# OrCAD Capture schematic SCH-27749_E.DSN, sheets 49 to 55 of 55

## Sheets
49 T4240 USB Ports: size C
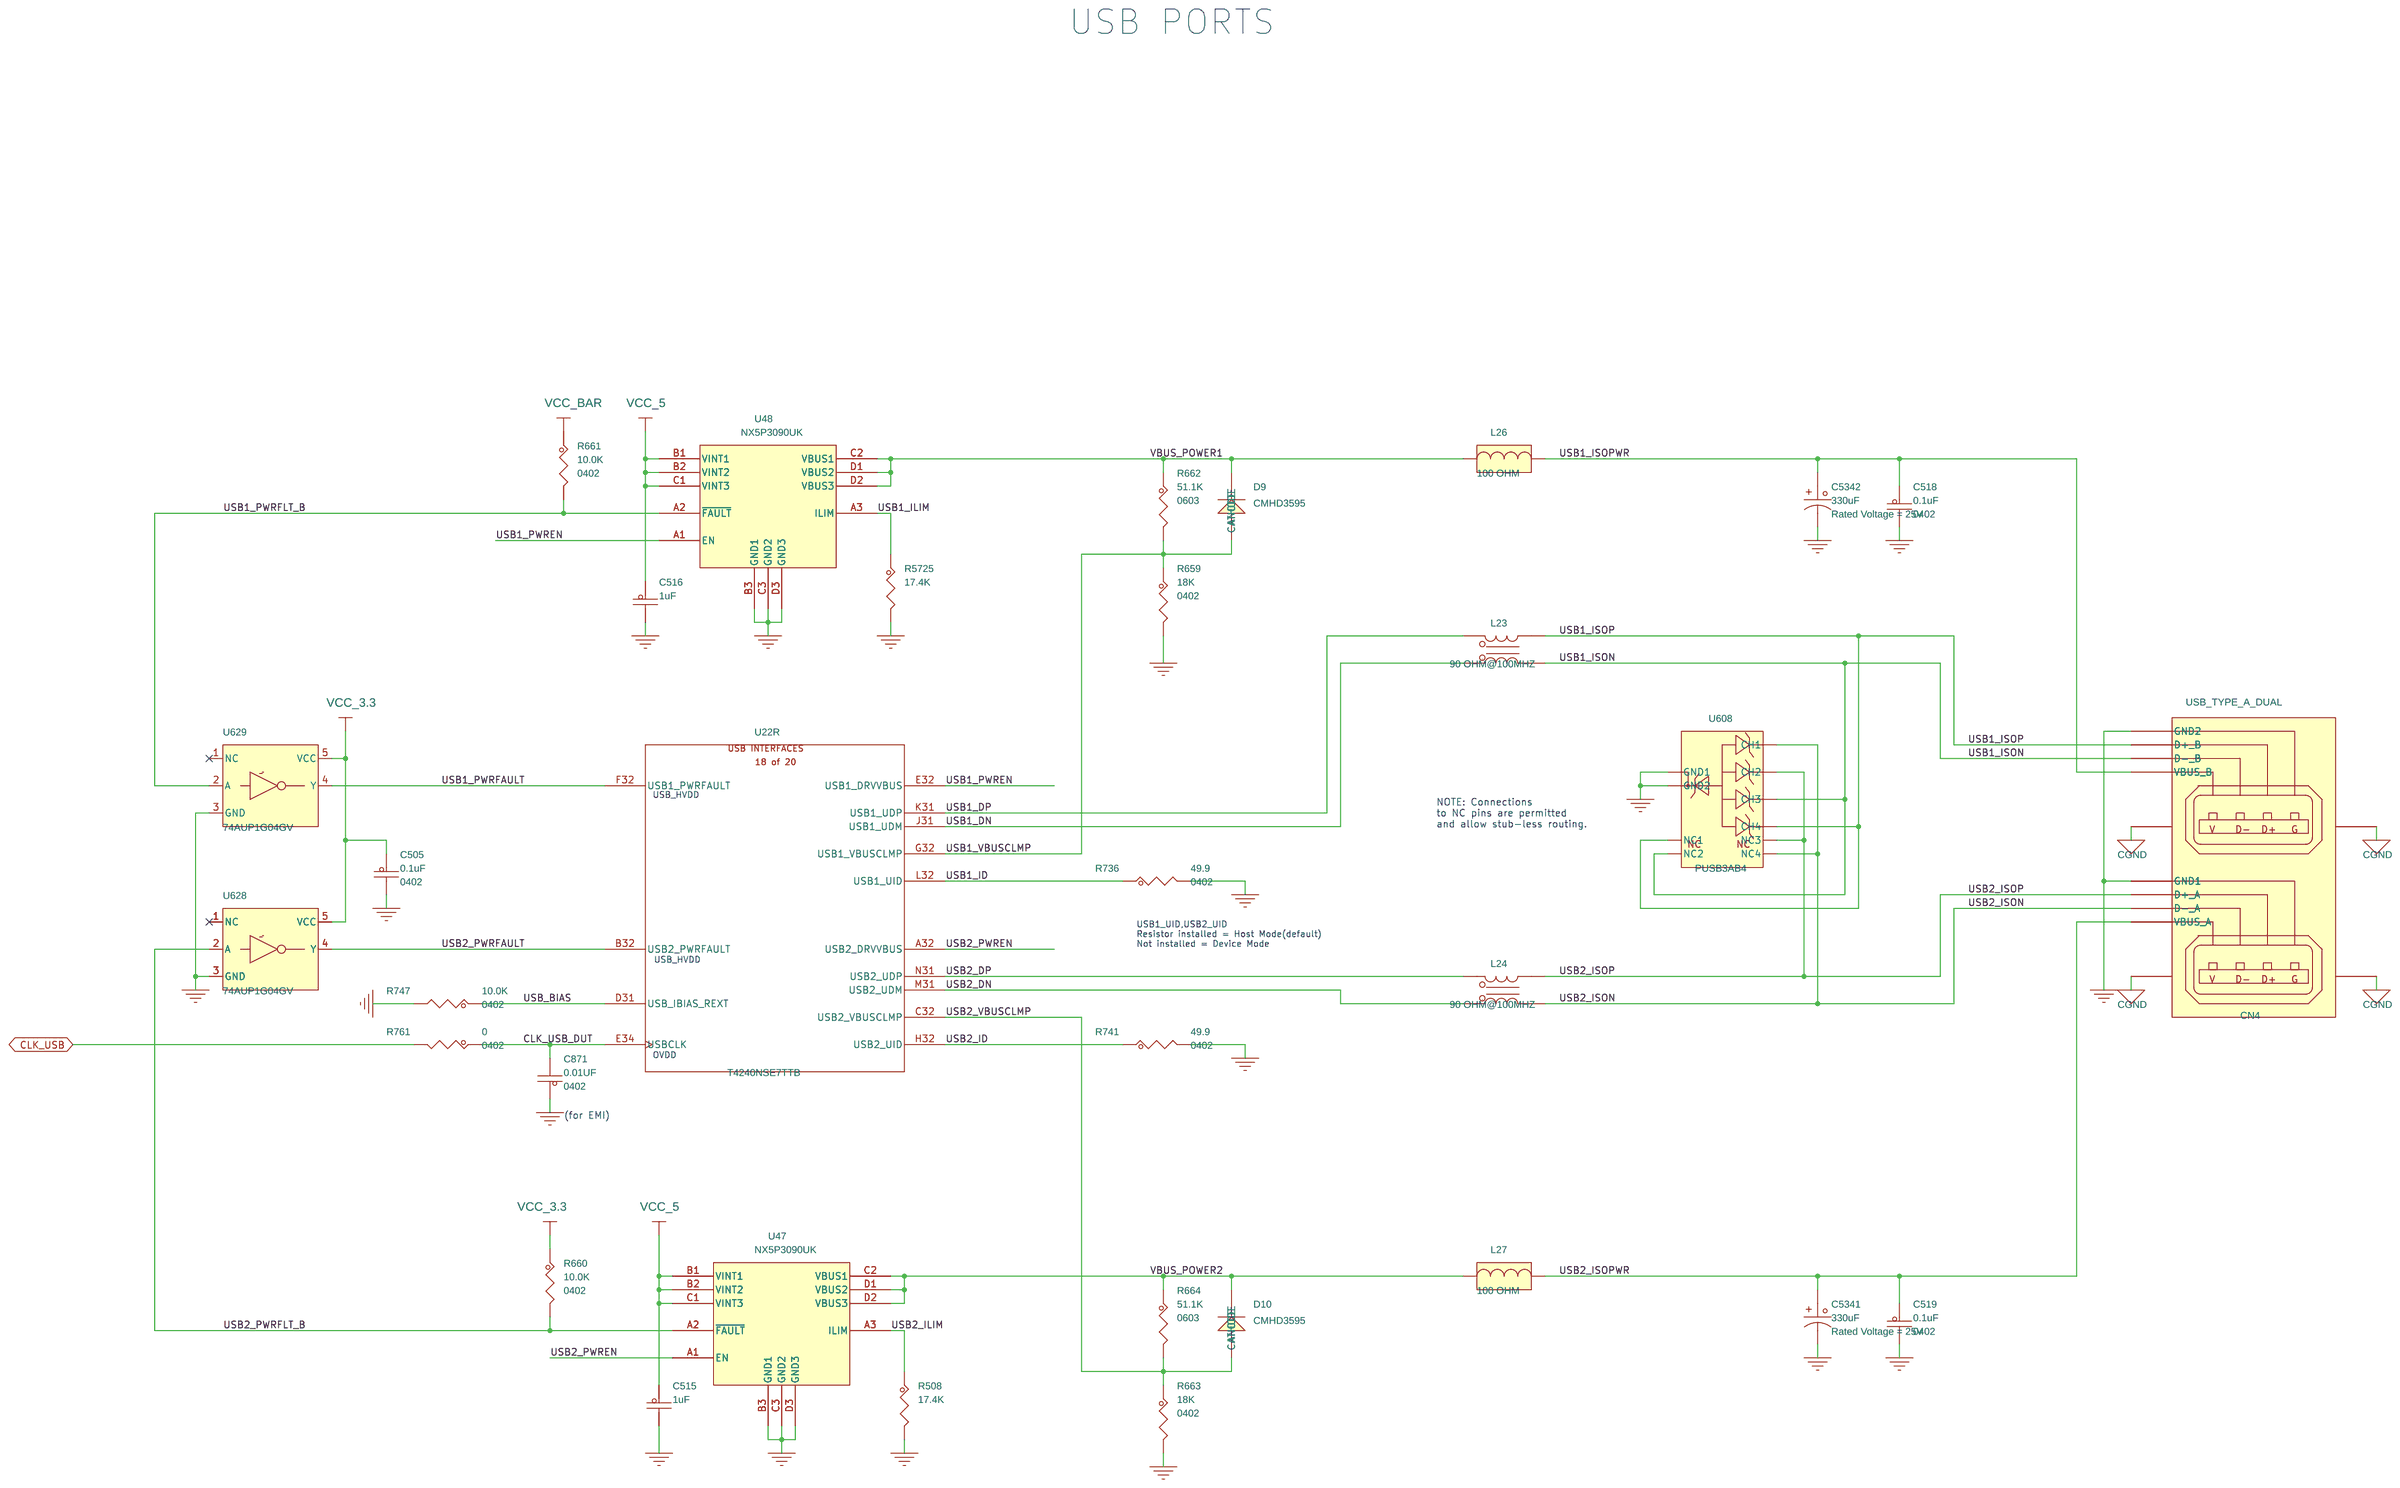
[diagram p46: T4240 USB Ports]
50 I2C Buf/Mux: size C
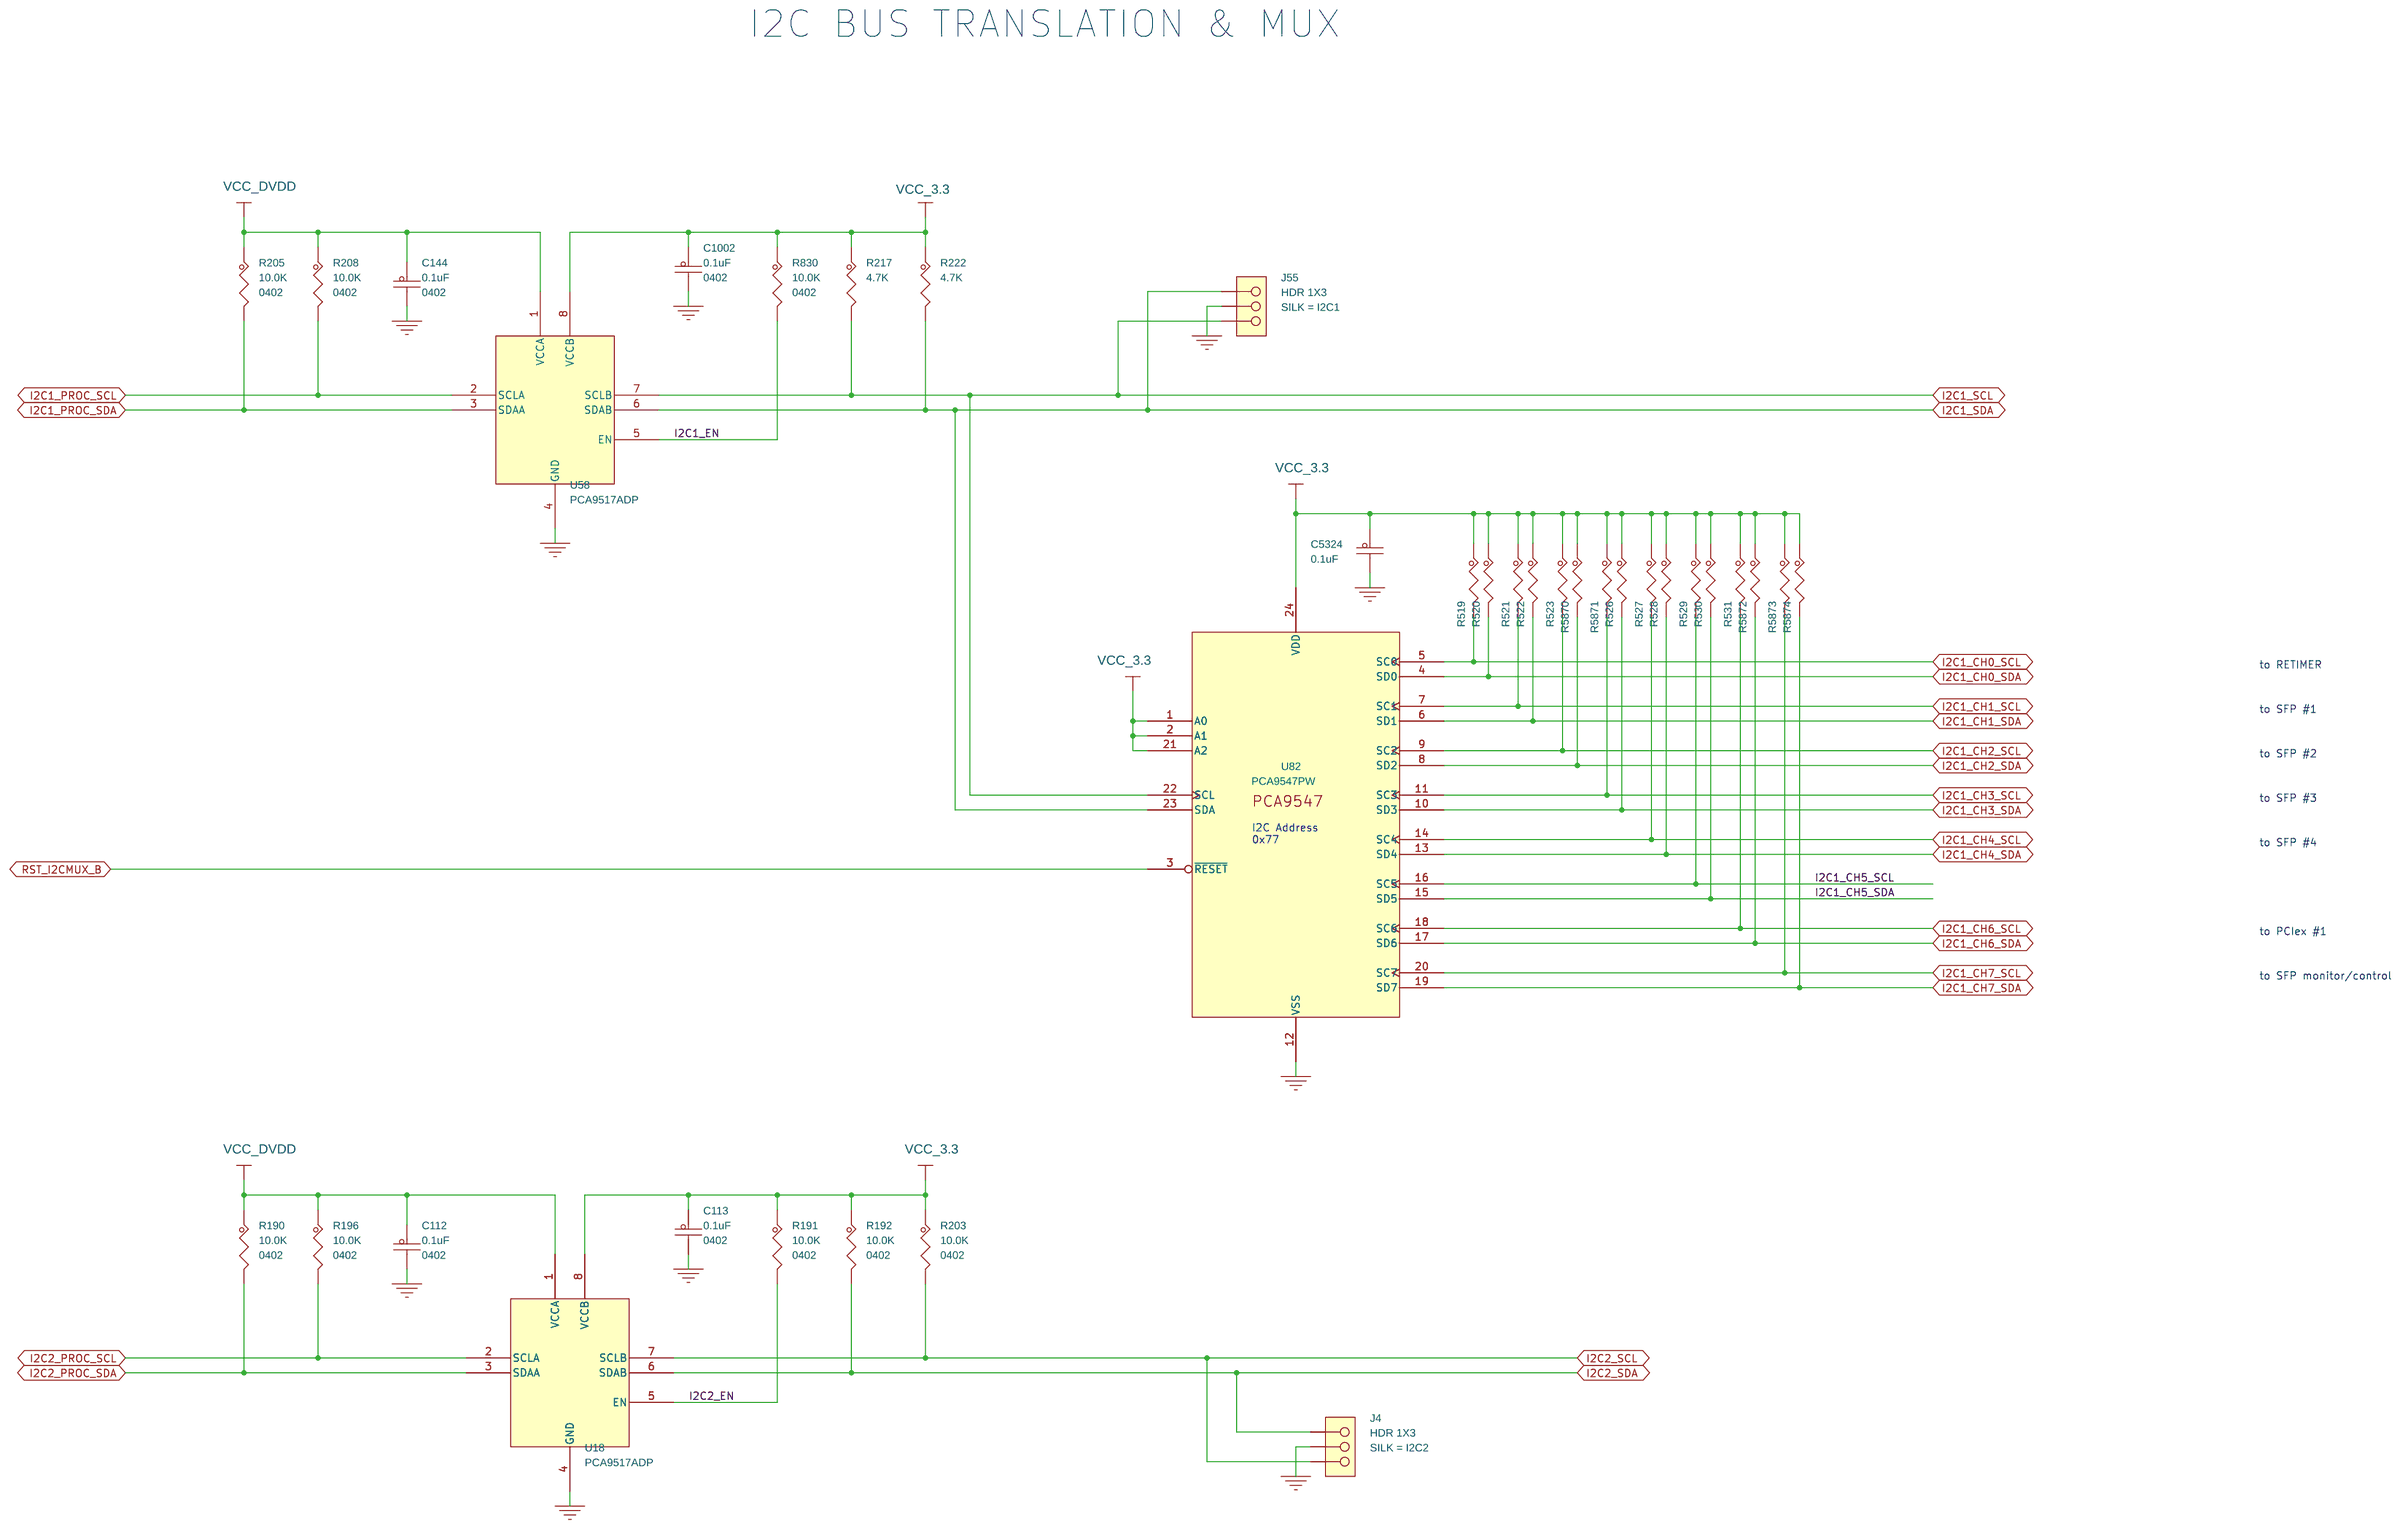
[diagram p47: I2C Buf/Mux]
51 I2C Devices: size C
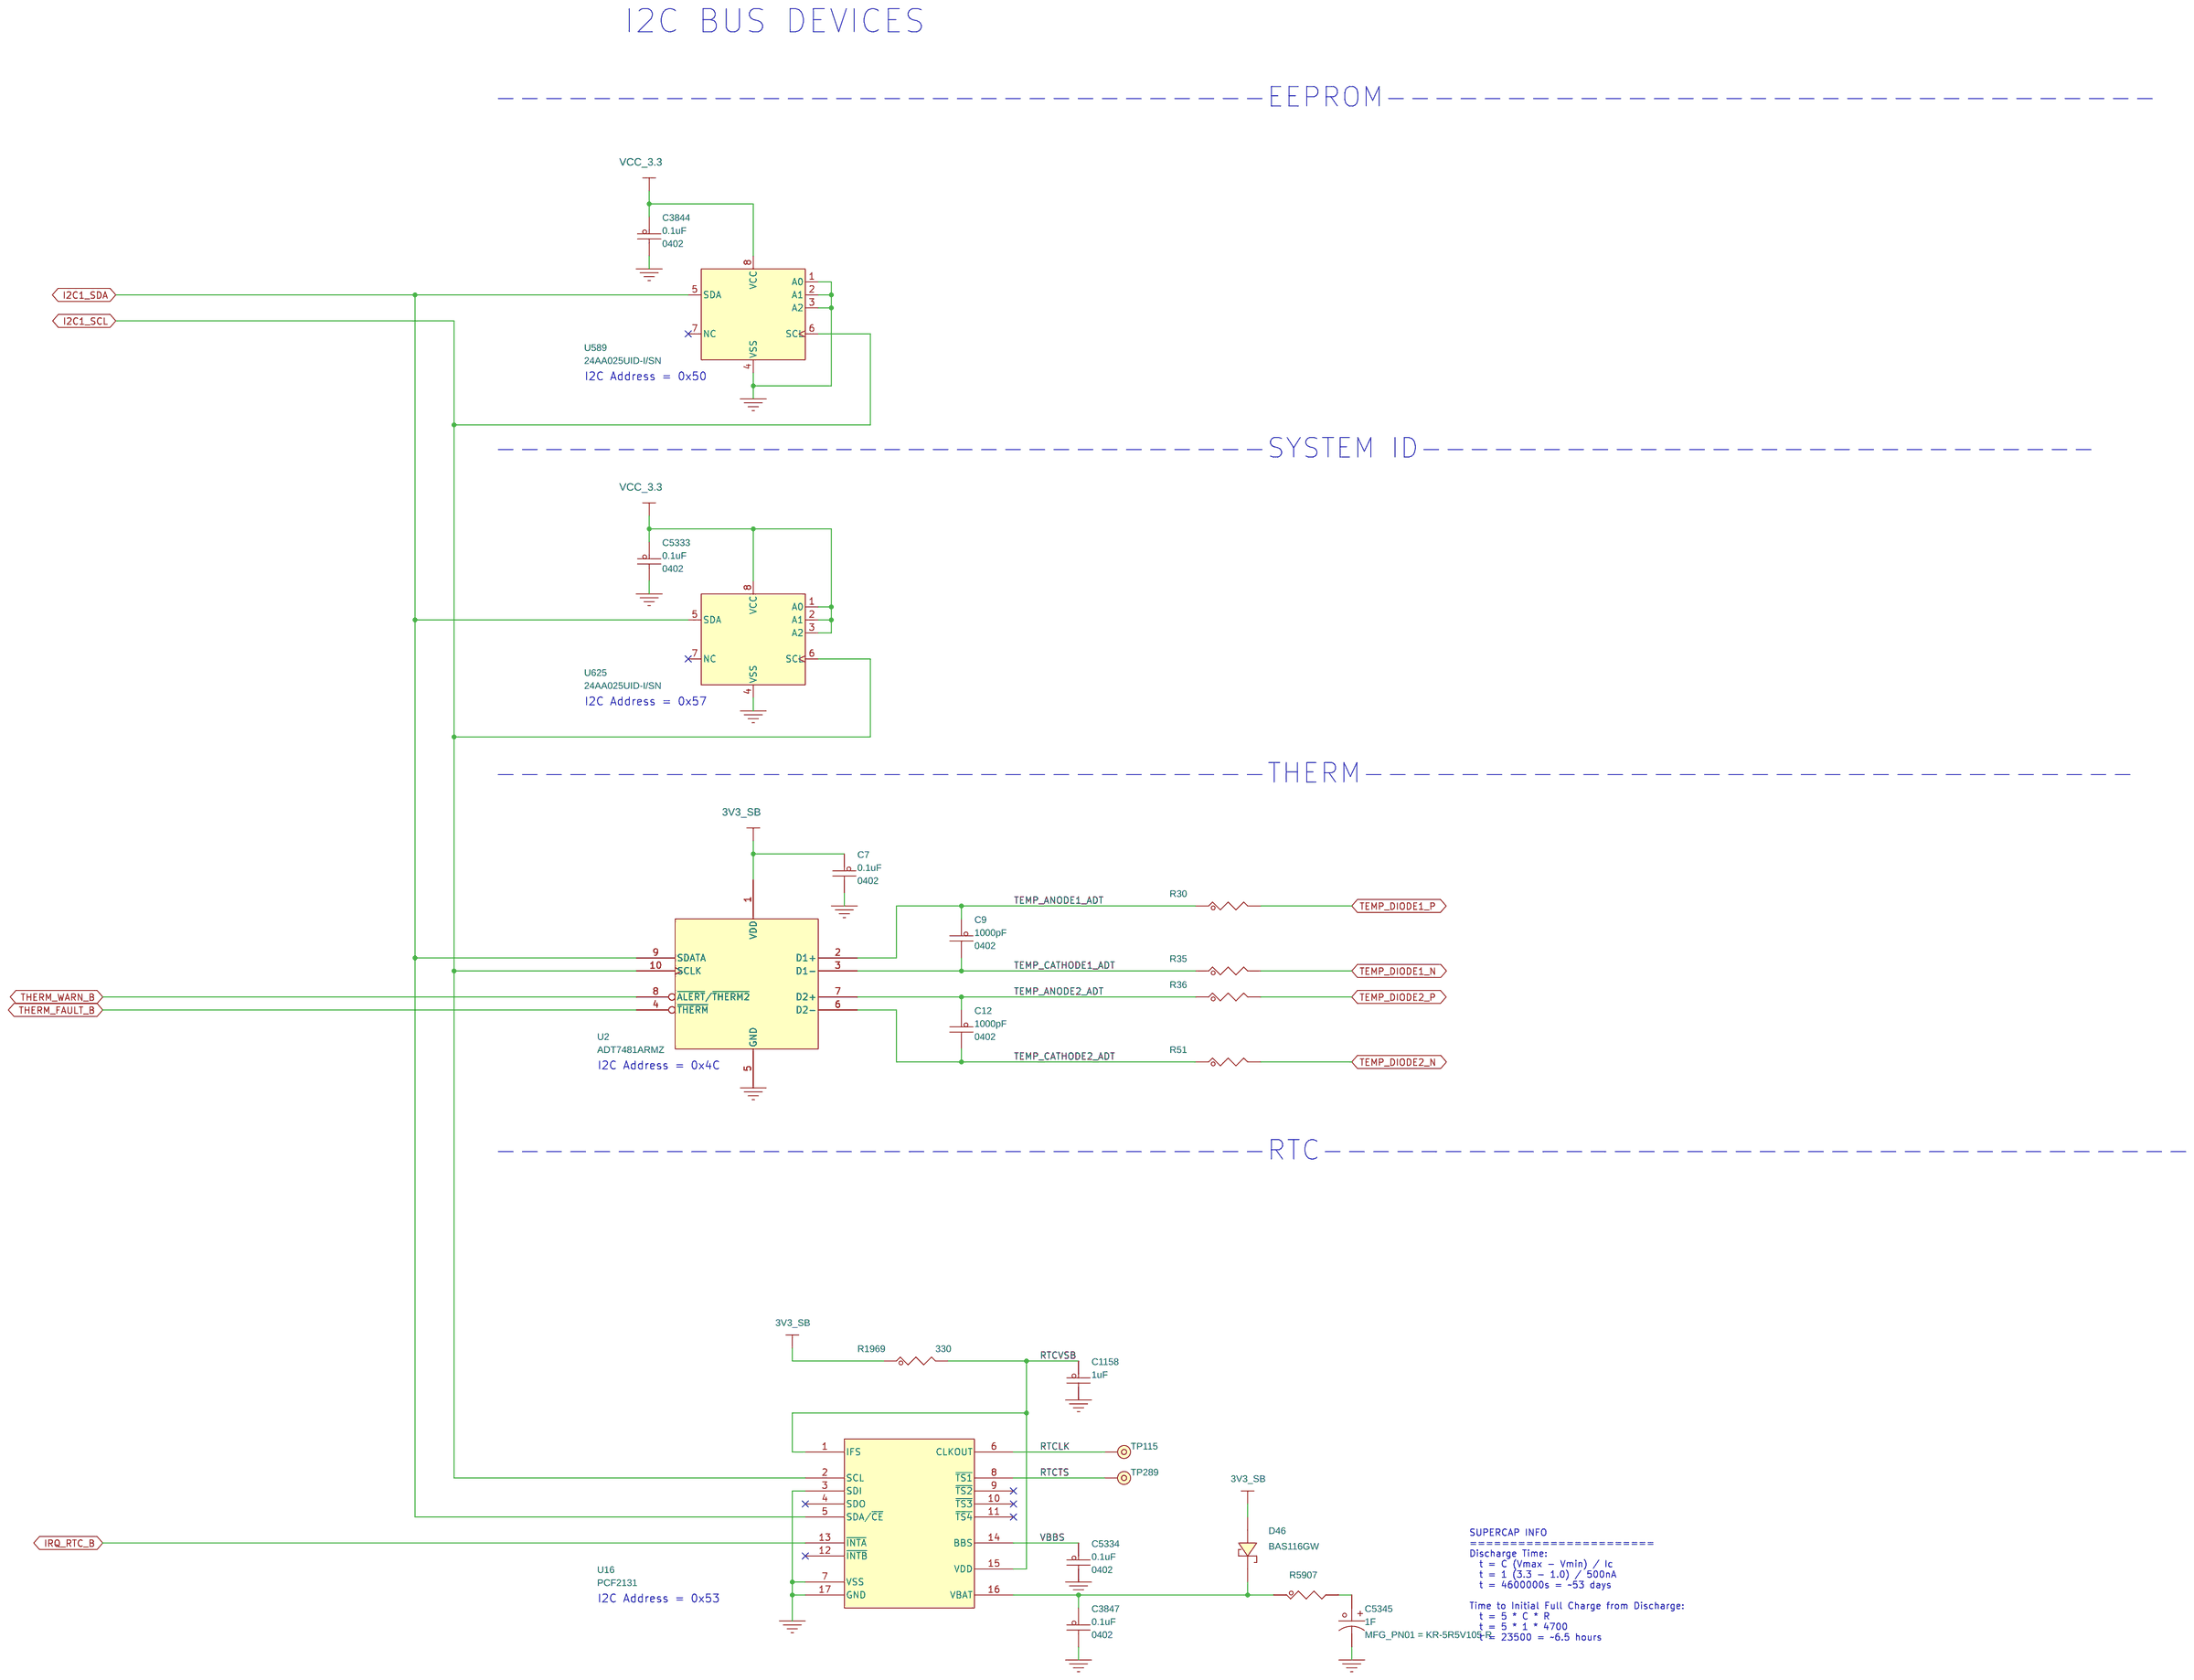
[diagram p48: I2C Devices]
52 Serial Ports: size C
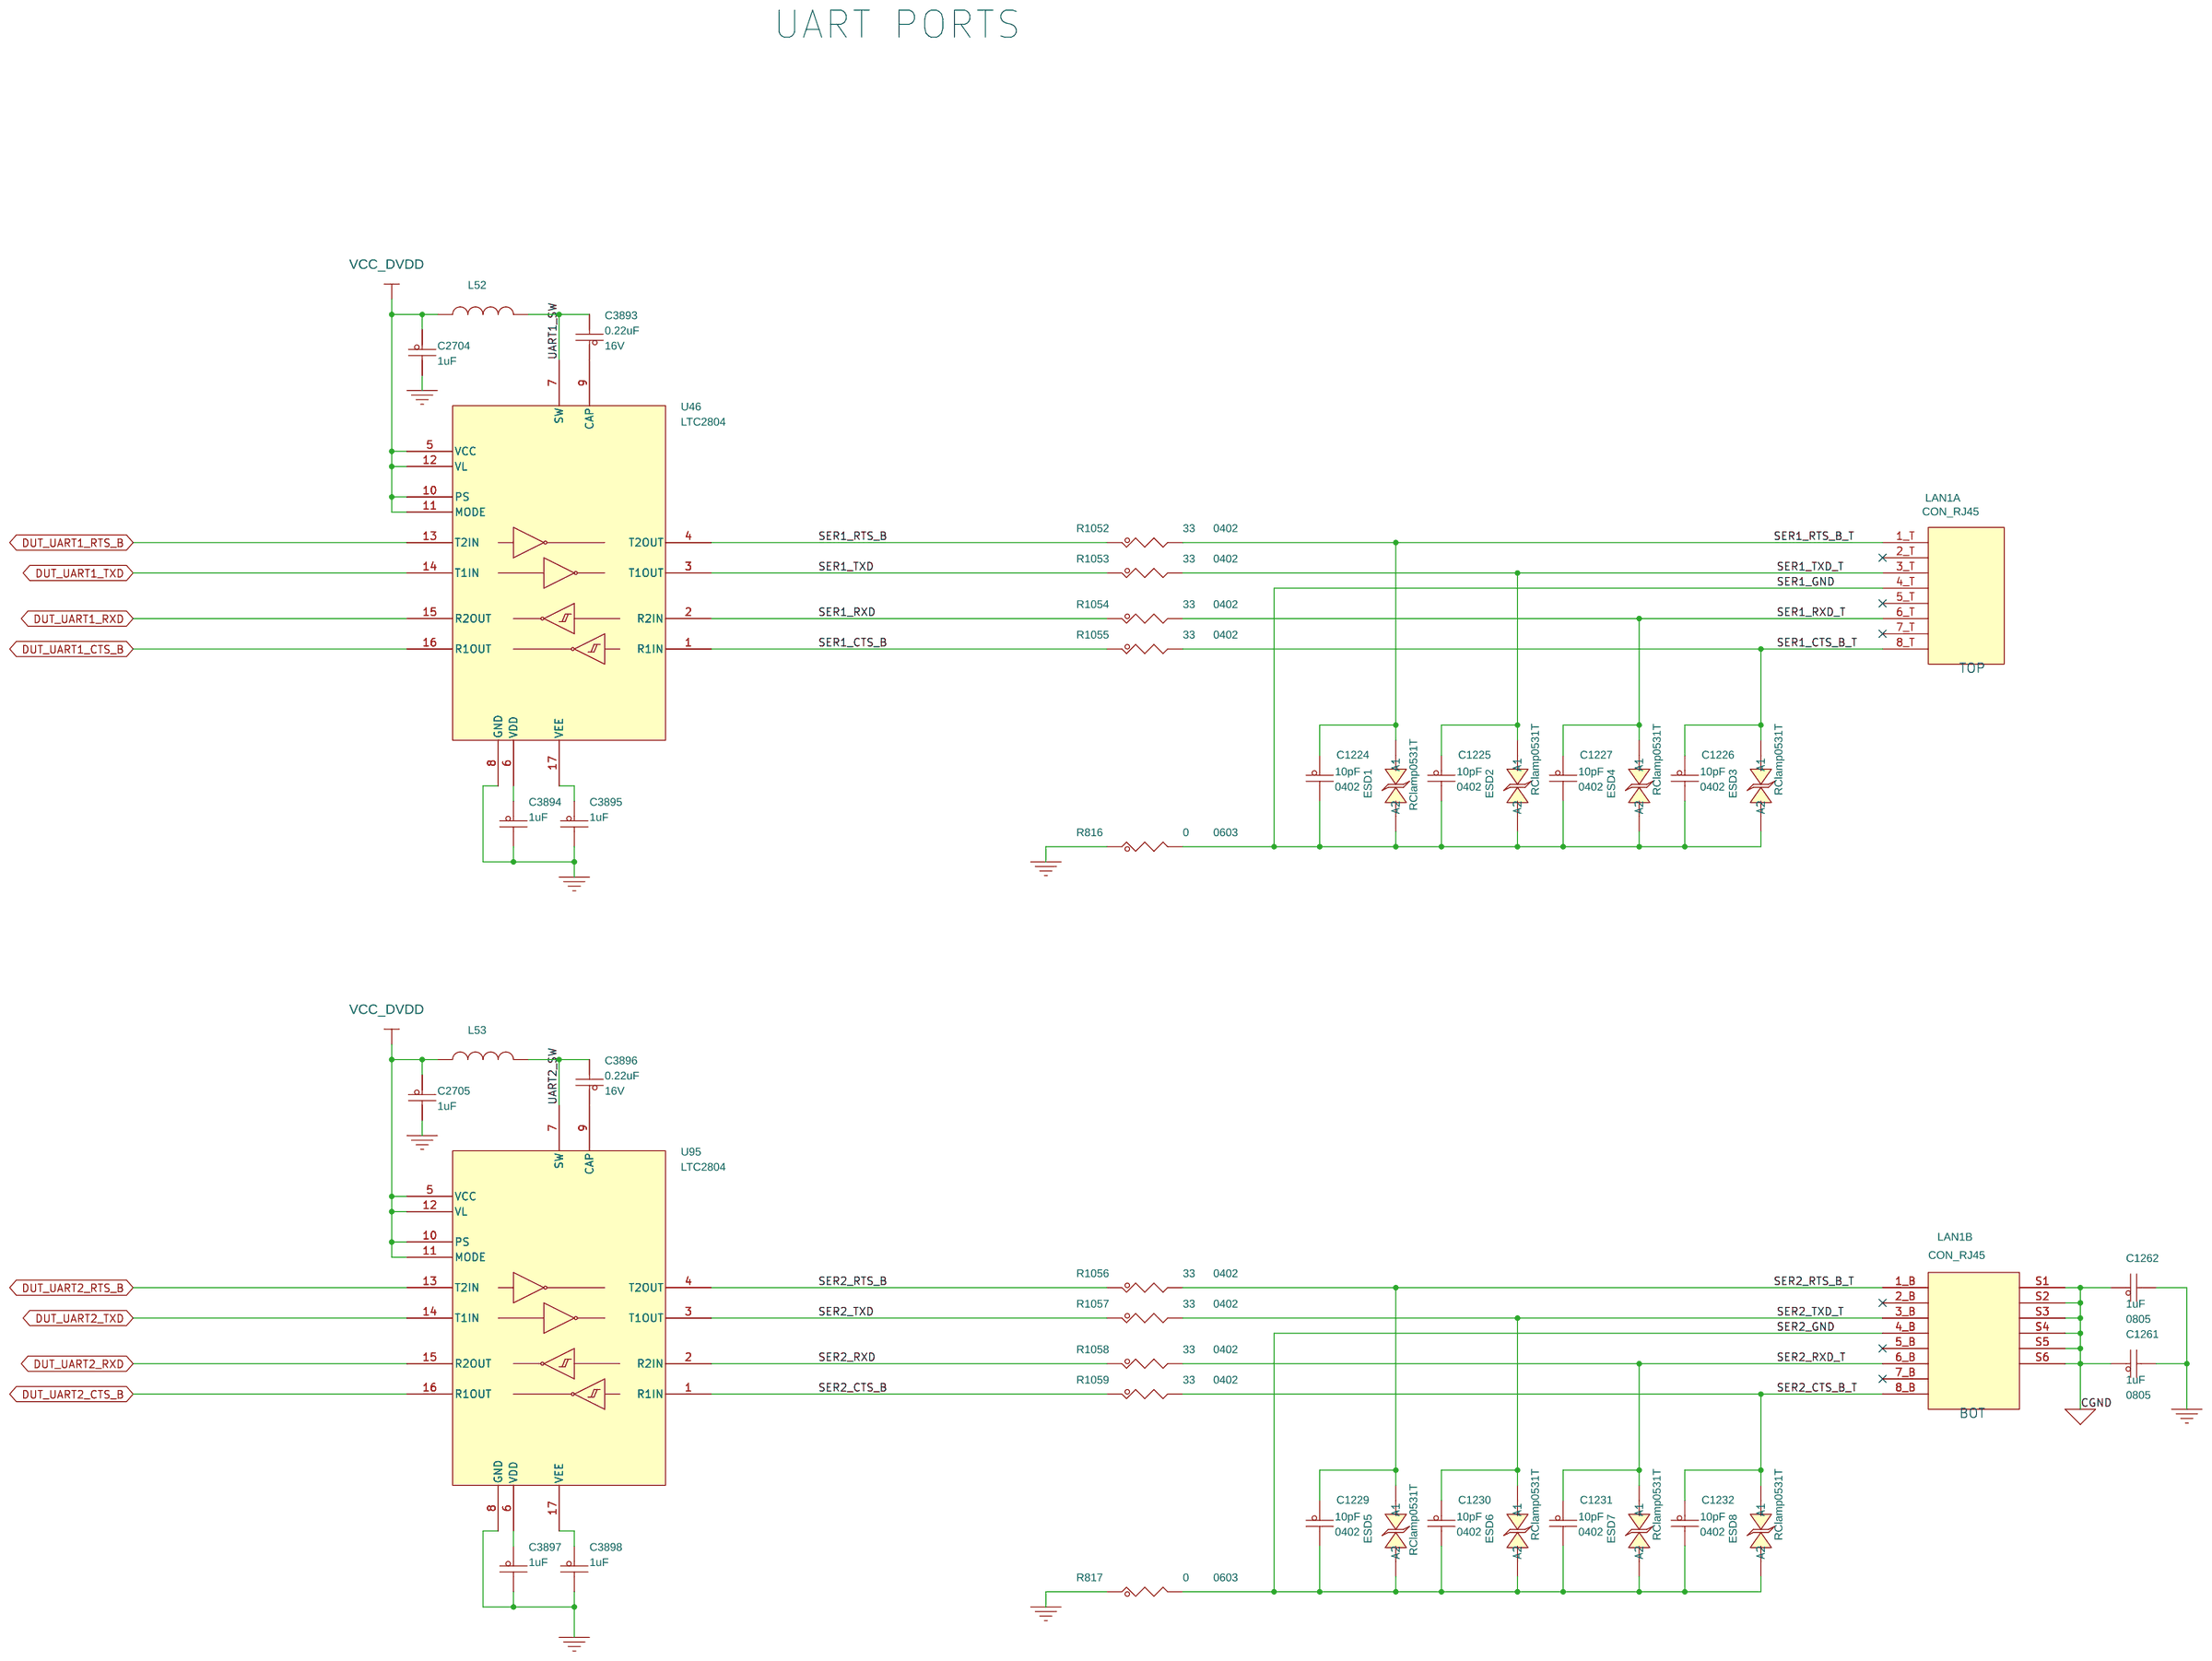
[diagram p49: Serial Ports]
53 Fan Controller & Fans: size C
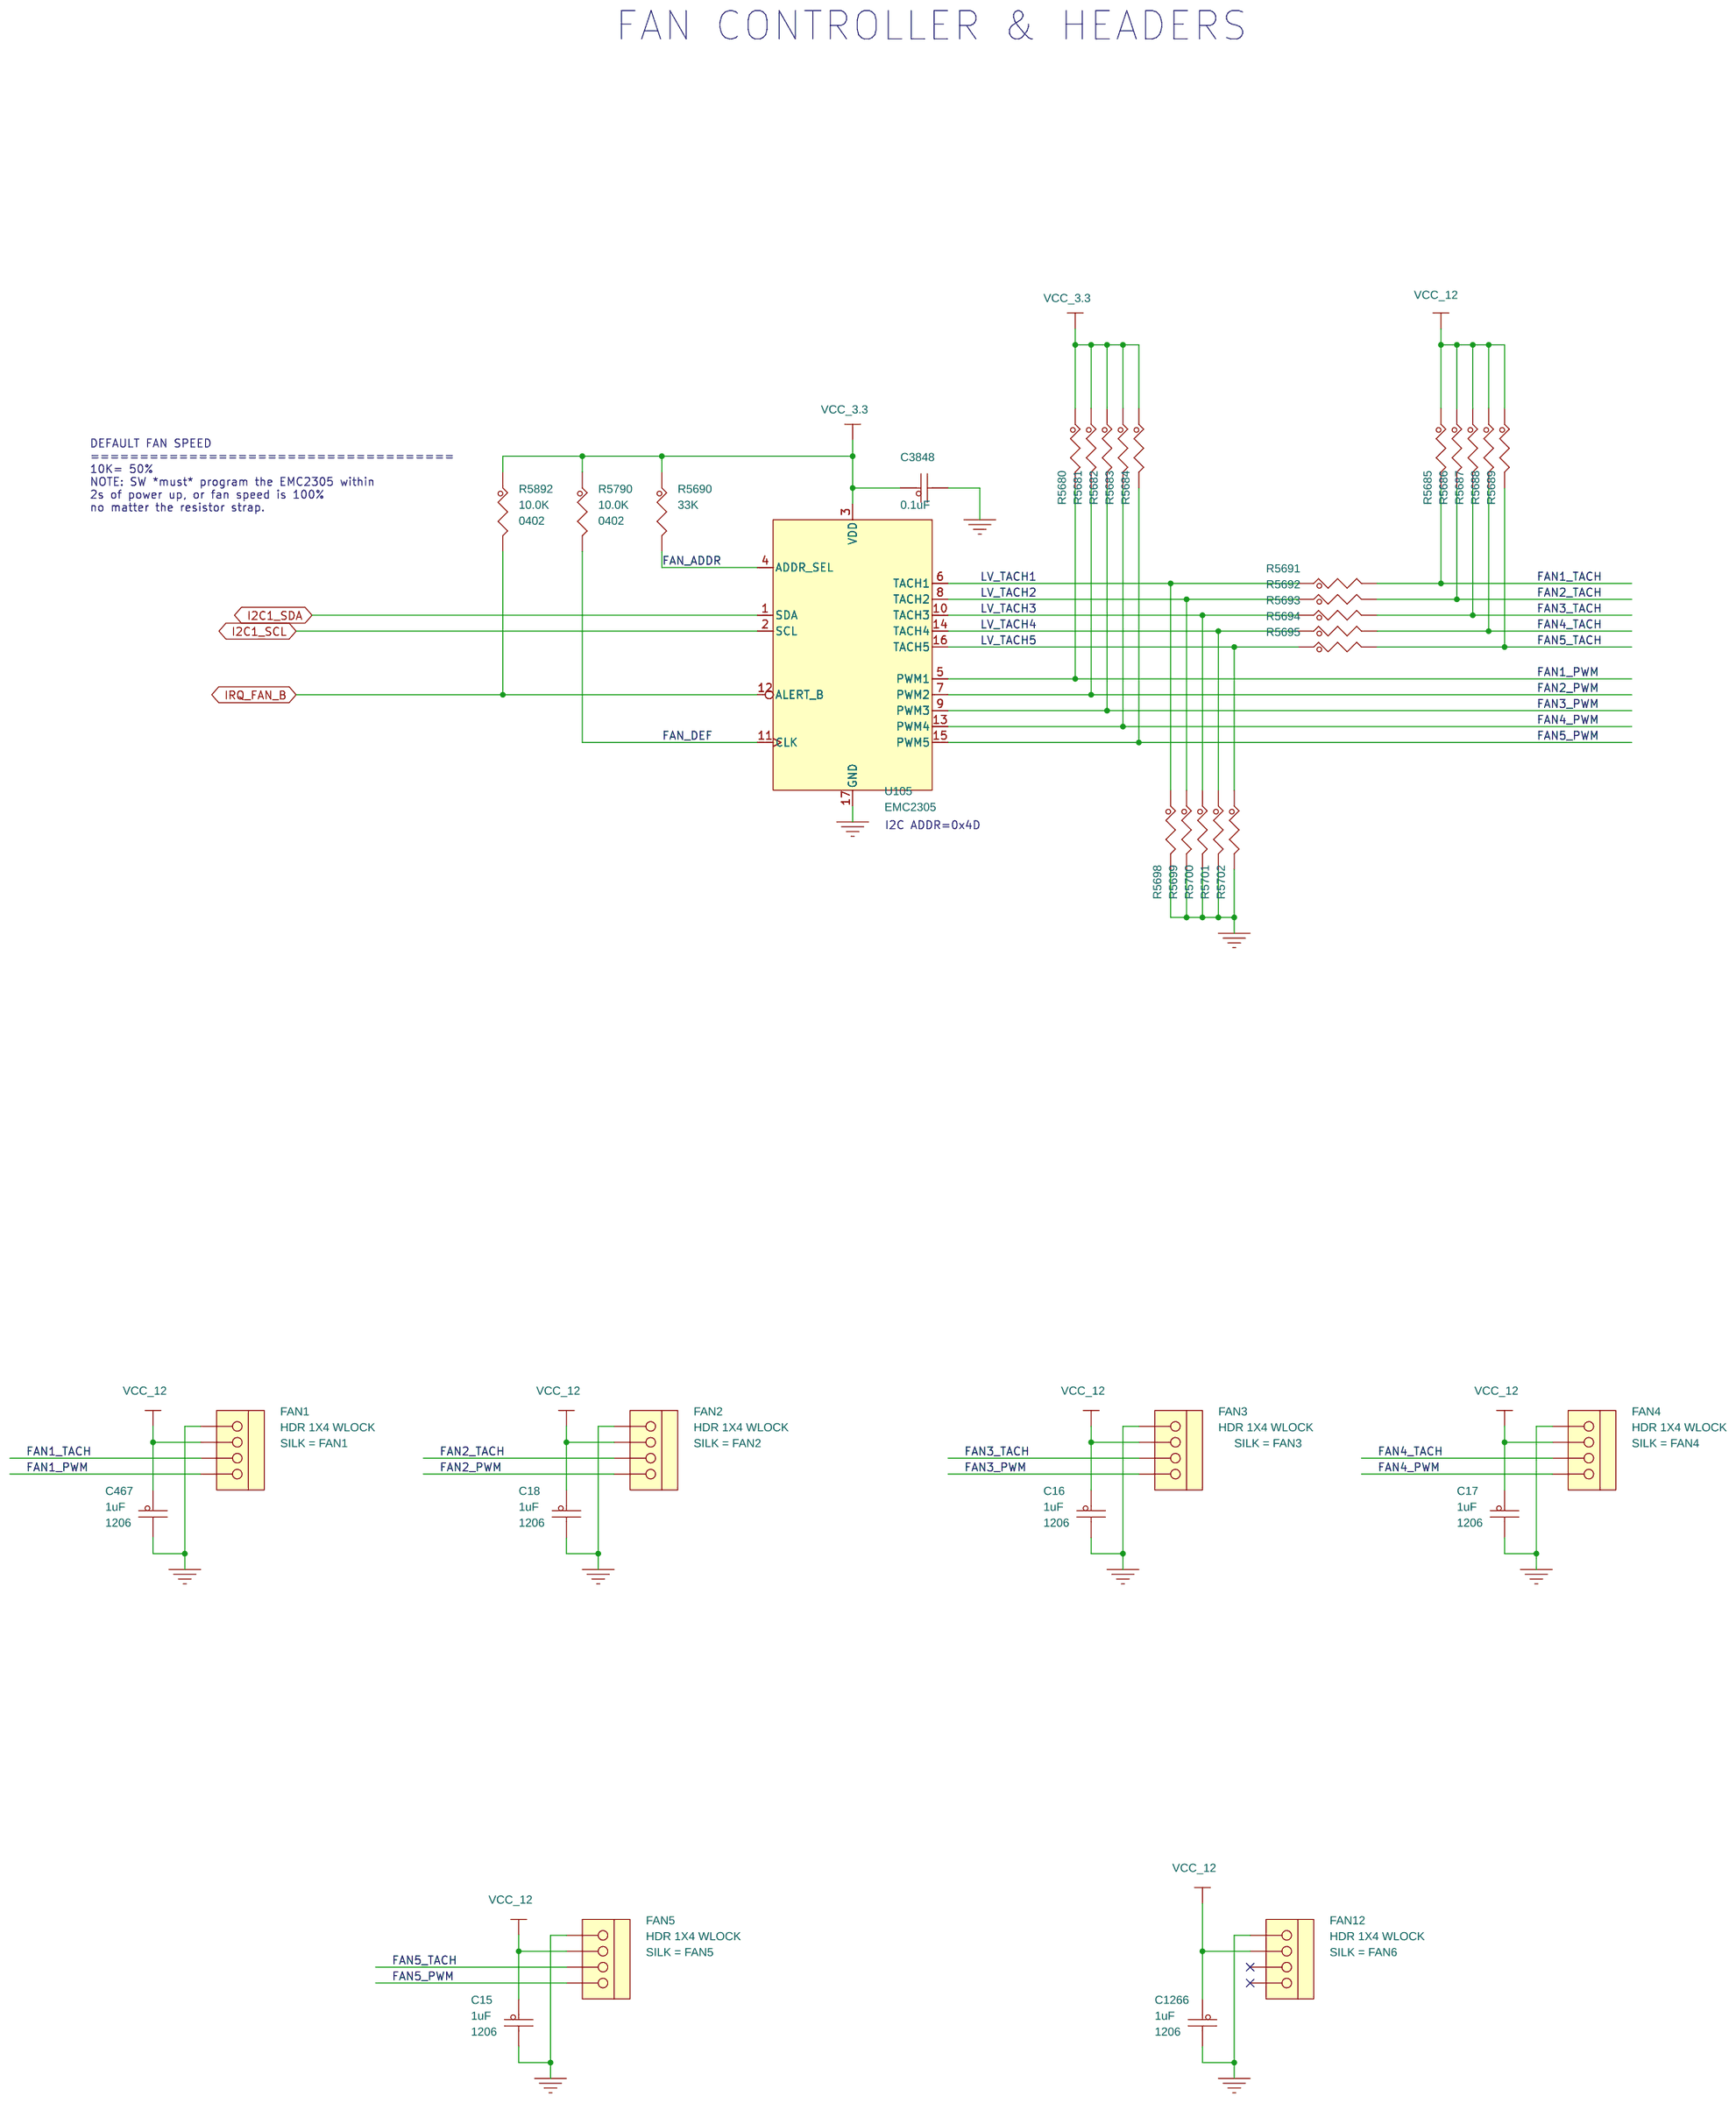
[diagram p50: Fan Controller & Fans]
54 LEDs: size C
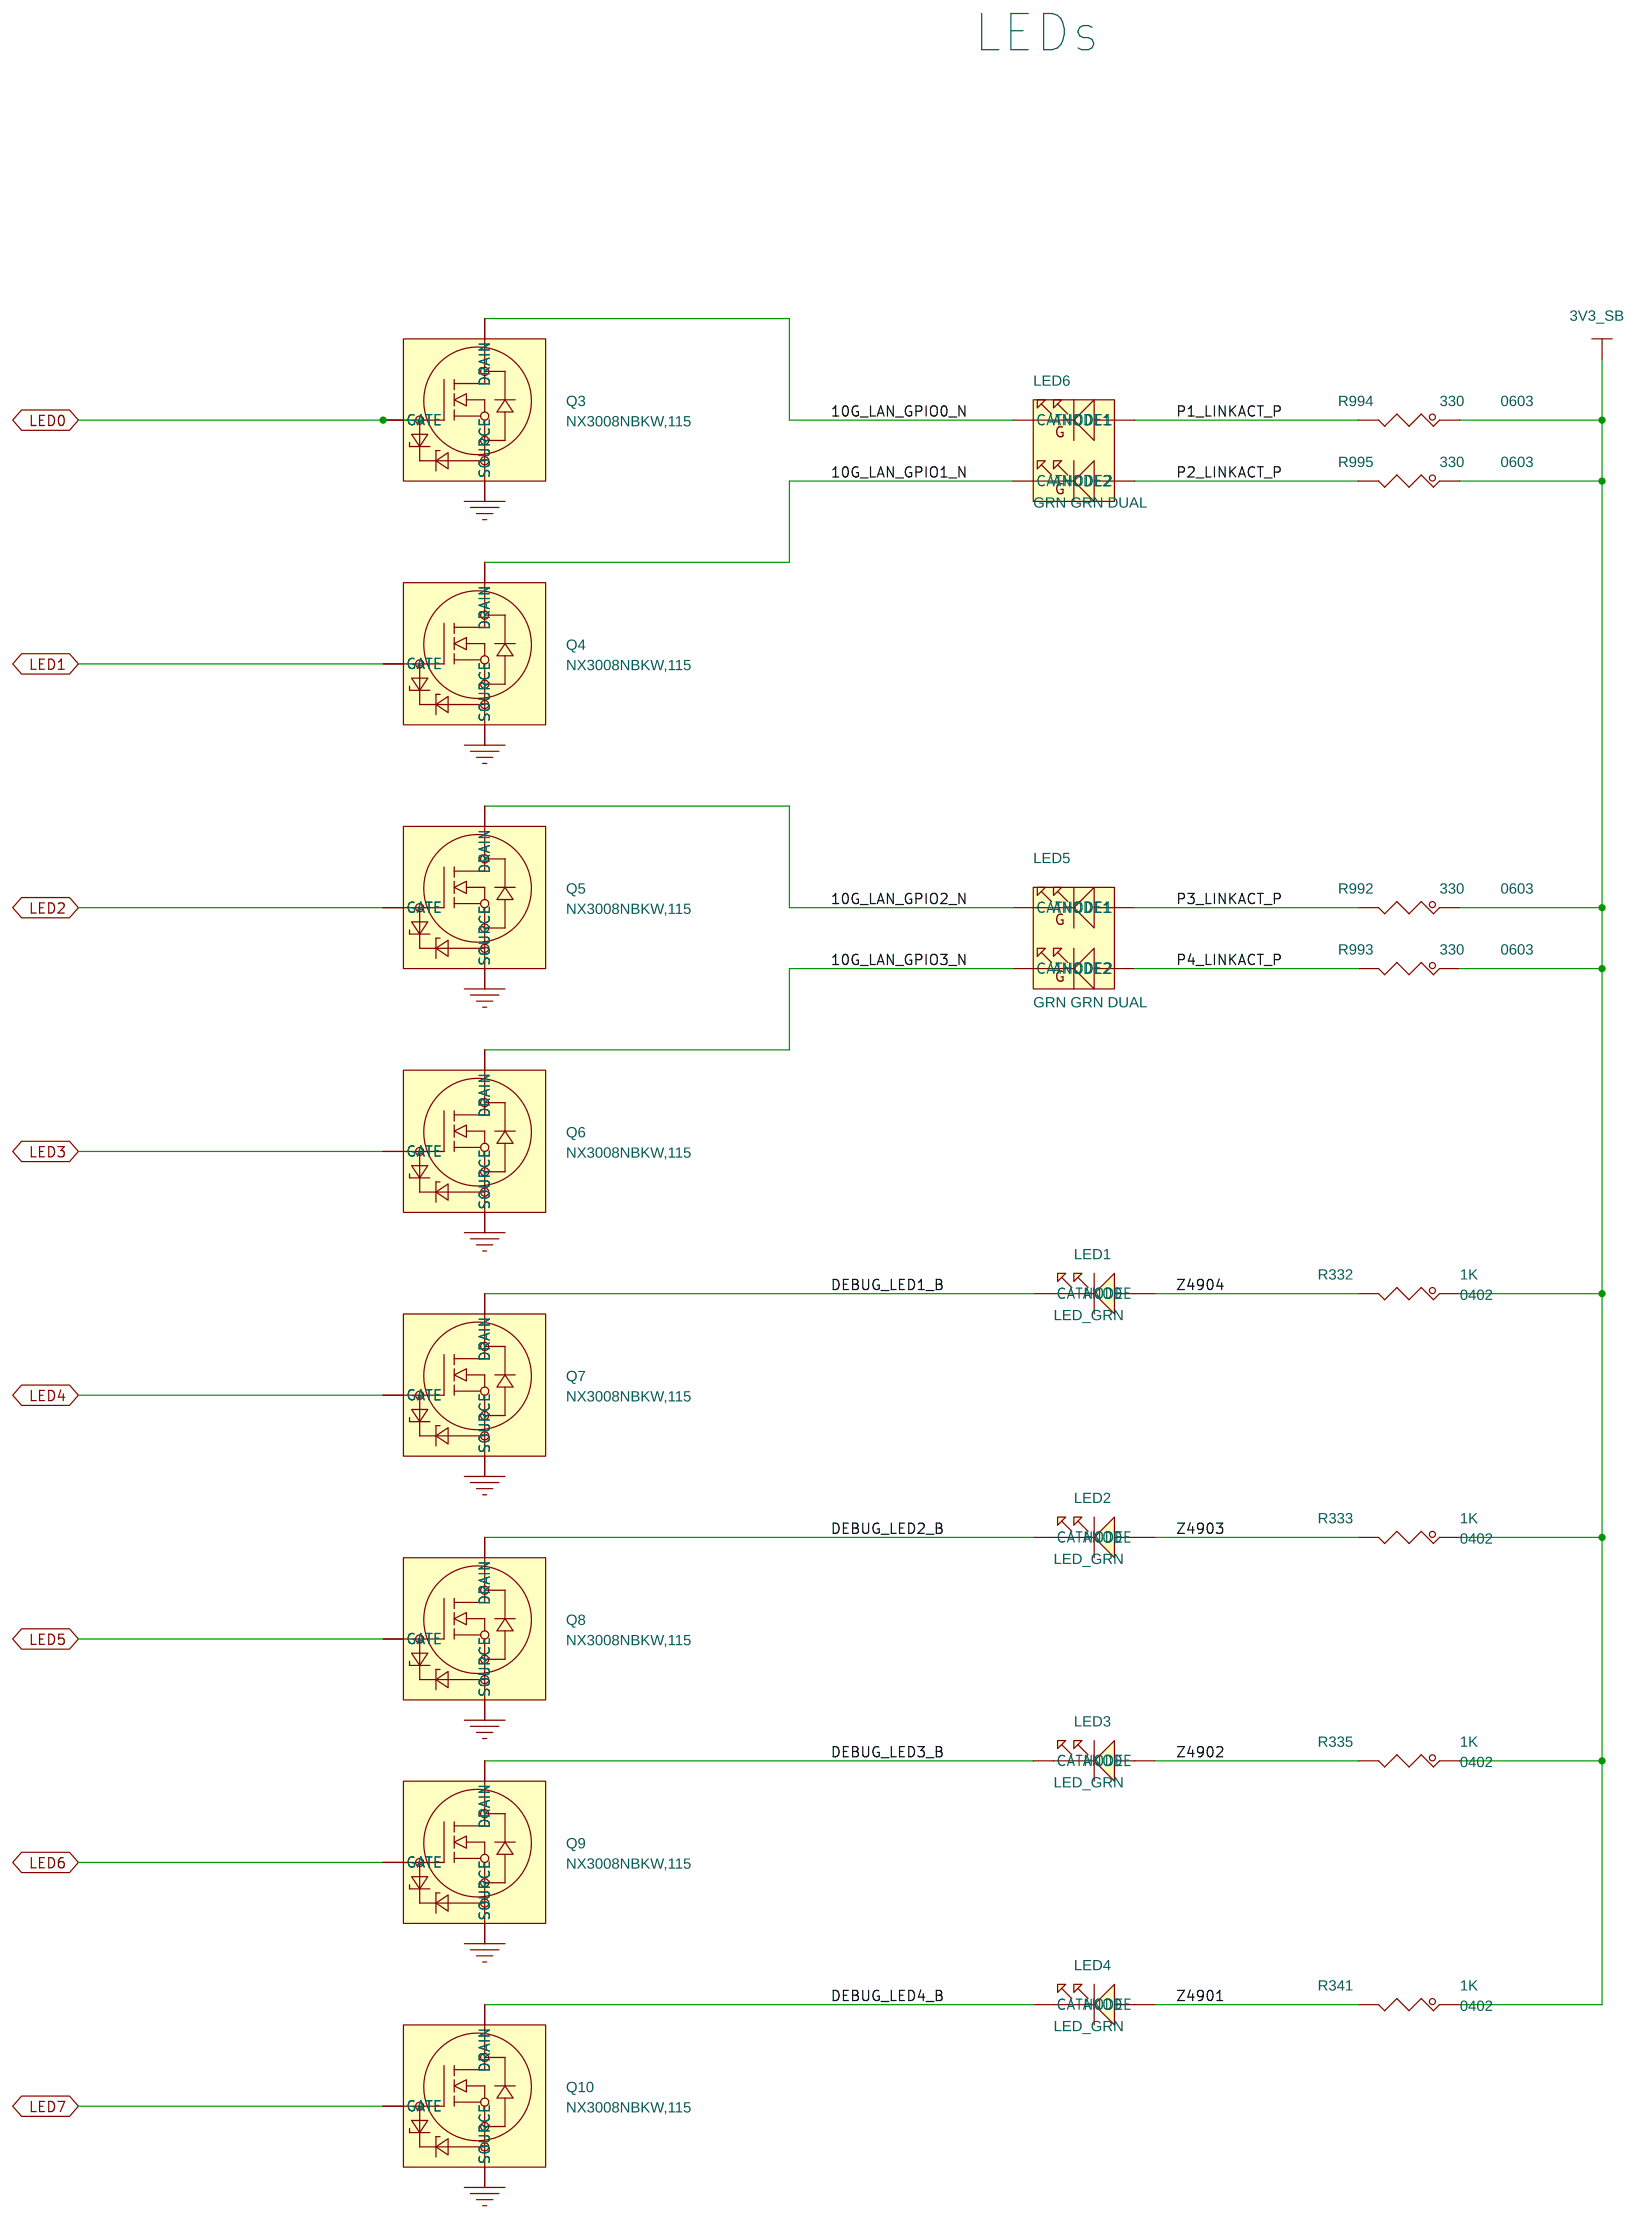
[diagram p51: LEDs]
55 ASY Config
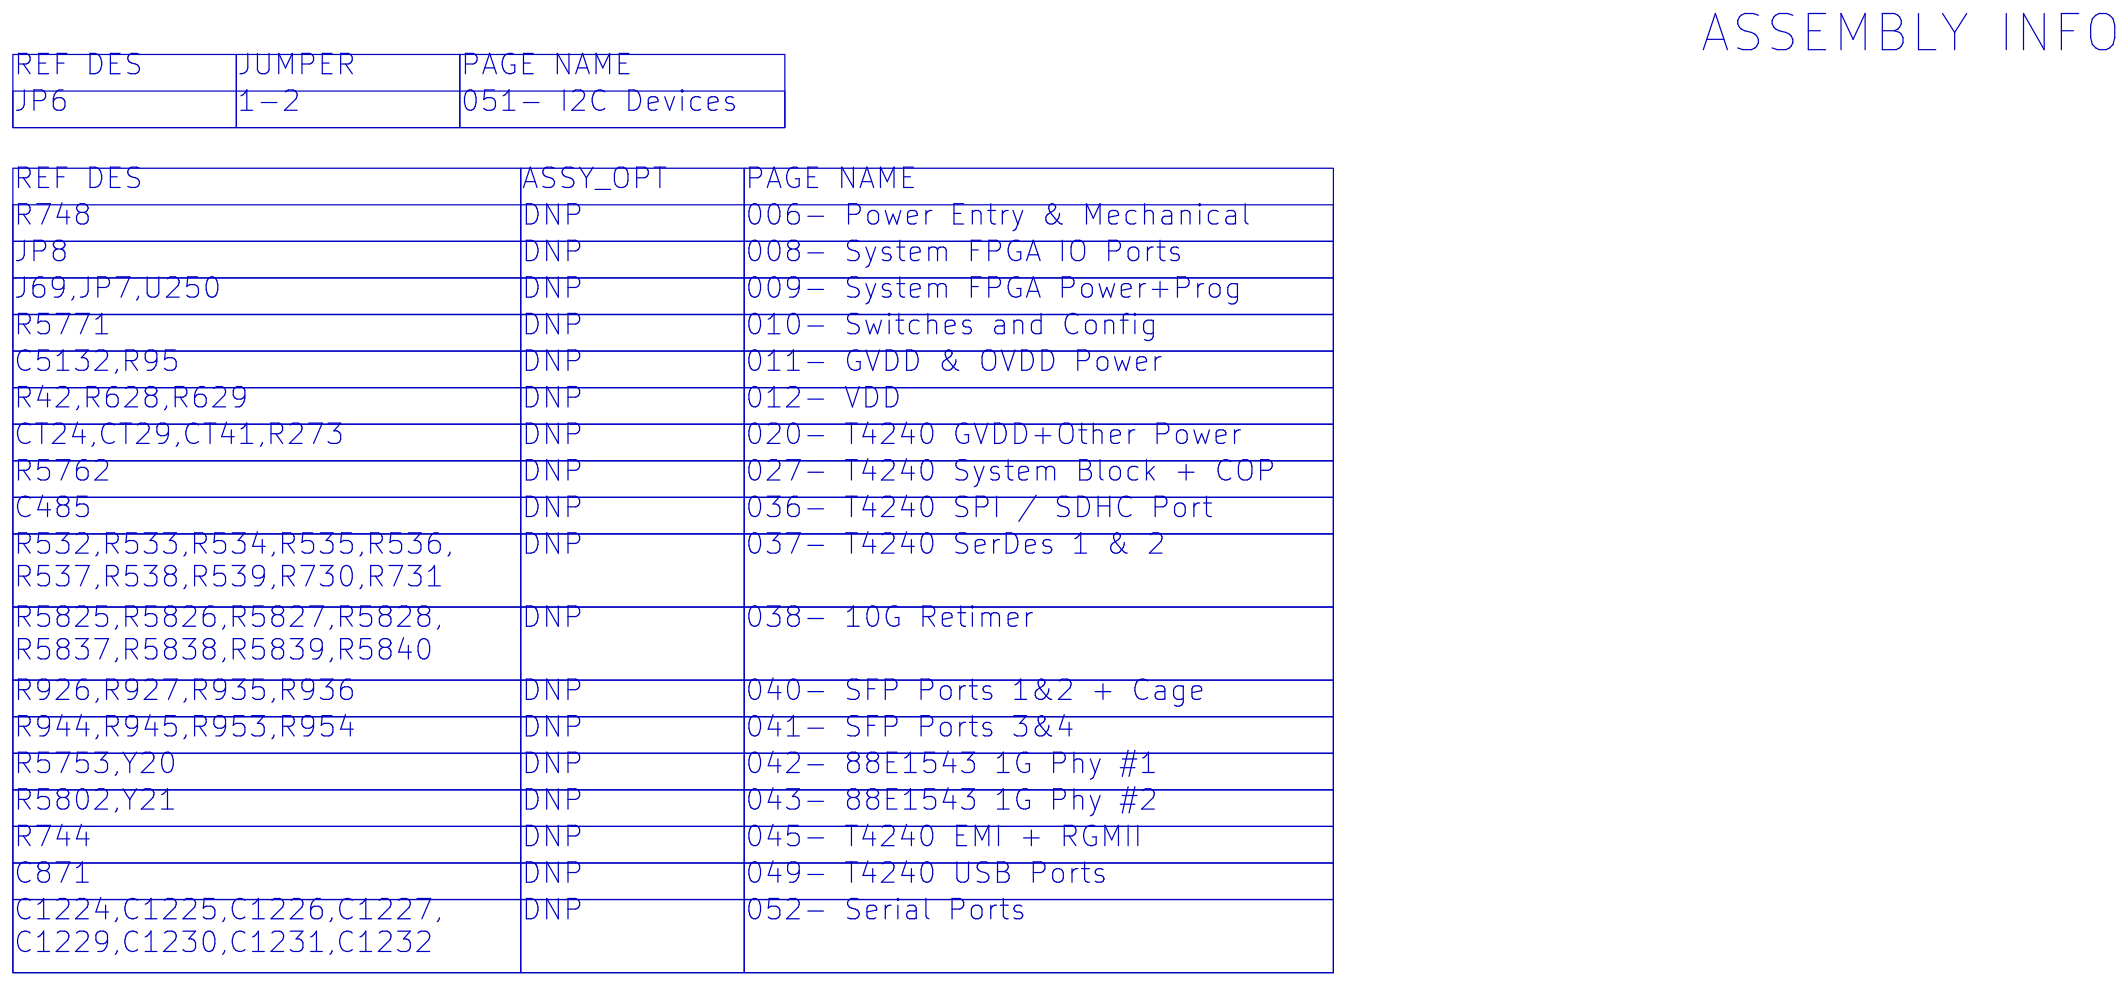
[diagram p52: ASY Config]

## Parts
sheet Fan Controller & Fans
C15  1uF  [CC0603_OV]
C16  1uF  [CC0603_OV]
C17  1uF  [CC0603_OV]
C18  1uF  [CC0603_OV]
C467  1uF  [CC0603_OV]
C1266  1uF  [CC0603_OV]
C3848  0.1uF  [CC0402_HD]
FAN1  HDR 1X4 WLOCK  [hdr4_2p54_th]
FAN2  HDR 1X4 WLOCK  [hdr4_2p54_th]
FAN3  HDR 1X4 WLOCK  [hdr4_2p54_th]
FAN4  HDR 1X4 WLOCK  [hdr4_2p54_th]
FAN5  HDR 1X4 WLOCK  [hdr4_2p54_th]
FAN12  HDR 1X4 WLOCK  [hdr4_2p54_th]
R5680  10.0K  [RC0402_25]
R5681  10.0K  [RC0402_25]
R5682  10.0K  [RC0402_25]
R5683  10.0K  [RC0402_25]
R5684  10.0K  [RC0402_25]
R5685  10.0K  [RC0402_25]
R5686  10.0K  [RC0402_25]
R5687  10.0K  [RC0402_25]
R5688  10.0K  [RC0402_25]
R5689  10.0K  [RC0402_25]
R5690  33K  [RC0402_25]
R5691  10.0K  [RC0402_25]
R5692  10.0K  [RC0402_25]
R5693  10.0K  [RC0402_25]
R5694  10.0K  [RC0402_25]
R5695  10.0K  [RC0402_25]
R5698  4.7K  [RC0402_25]
R5699  4.7K  [RC0402_25]
R5700  4.7K  [RC0402_25]
R5701  4.7K  [RC0402_25]
R5702  4.7K  [RC0402_25]
R5790  10.0K  [RC0402_25]
R5892  10.0K  [RC0402_25]
U105  EMC2305  [tqfn16_0p65_4x4mm_tab]
sheet I2C Buf/Mux
C112  0.1uF  [CC0402_HD]
C113  0.1uF  [CC0402_HD]
C144  0.1uF  [CC0402_HD]
C1002  0.1uF  [CC0402_HD]
C5324  0.1uF  [CC0402_HD]
J4  HDR 1X3  [hdr1x3_50mil_335h]
J55  HDR 1X3  [hdr1x3_50mil_335h]
R190  10.0K  [RC0402_25]
R191  10.0K  [RC0402_25]
R192  10.0K  [RC0402_25]
R196  10.0K  [RC0402_25]
R203  10.0K  [RC0402_25]
R205  10.0K  [RC0402_25]
R208  10.0K  [RC0402_25]
R217  4.7K  [RC0402_25]
R222  4.7K  [RC0402_25]
R519  4.7K  [RC0402_25]
R520  4.7K  [RC0402_25]
R521  4.7K  [RC0402_25]
R522  4.7K  [RC0402_25]
R523  4.7K  [RC0402_25]
R526  4.7K  [RC0402_25]
R527  4.7K  [RC0402_25]
R528  4.7K  [RC0402_25]
R529  4.7K  [RC0402_25]
R530  4.7K  [RC0402_25]
R531  4.7K  [RC0402_25]
R830  10.0K  [RC0402_25]
R5870  4.7K  [RC0402_25]
R5871  4.7K  [RC0402_25]
R5872  4.7K  [RC0402_25]
R5873  4.7K  [RC0402_25]
R5874  4.7K  [RC0402_25]
U18  PCA9517ADP  [tssop8_a]
U58  PCA9517ADP  [tssop8_a]
U82  PCA9547PW  [tssop24_0p65_7p9x4p5]
sheet I2C Devices
C7  0.1uF  [CC0402_HD]
C9  1000pF  [CC0402_HD]
C12  1000pF  [CC0402_HD]
C1158  1uF  [CC0402_HD]
C3844  0.1uF  [CC0402_HD]
C3847  0.1uF  [CC0402_HD]
C5333  0.1uF  [CC0402_HD]
C5334  0.1uF  [CC0402_HD]
C5345  1F  [cap_5x19p2_th]
D46  BAS116GW  [SOD-123]
R30  10.0  [RC0402_25]
R35  10.0  [RC0402_25]
R36  10.0  [RC0402_25]
R51  10.0  [RC0402_25]
R1969  330  [RC0402_25]
R5907  4.7K  [RC0402_25]
TP115  TPAD_020  [tpad_020_top]
TP289  TPAD_020  [tpad_020_top]
U2  ADT7481ARMZ  [MSOP10_60X12]
U16  PCF2131  [so16_0p5_3p5x4p5_mm]
U589  24AA025UID-I/SN  [SO8_1P27_4X5]
U625  24AA025UID-I/SN  [SO8_1P27_4X5]
sheet LEDs
LED1  LED_GRN  [LED_0603]
LED2  LED_GRN  [LED_0603]
LED3  LED_GRN  [LED_0603]
LED4  LED_GRN  [LED_0603]
LED5  GRN GRN DUAL  [led_dual_553_th]
LED6  GRN GRN DUAL  [led_dual_553_th]
Q3  NX3008NBKW,115  [sc70_3]
Q4  NX3008NBKW,115  [sc70_3]
Q5  NX3008NBKW,115  [sc70_3]
Q6  NX3008NBKW,115  [sc70_3]
Q7  NX3008NBKW,115  [sc70_3]
Q8  NX3008NBKW,115  [sc70_3]
Q9  NX3008NBKW,115  [sc70_3]
Q10  NX3008NBKW,115  [sc70_3]
R332  1K  [RC0402_25]
R333  1K  [RC0402_25]
R335  1K  [RC0402_25]
R341  1K  [RC0402_25]
R992  330  [RC0402_25]
R993  330  [RC0402_25]
R994  330  [RC0402_25]
R995  330  [RC0402_25]
sheet Serial Ports
C1224  10pF  [cc0402_hd]
C1225  10pF  [cc0402_hd]
C1226  10pF  [cc0402_hd]
C1227  10pF  [cc0402_hd]
C1229  10pF  [cc0402_hd]
C1230  10pF  [cc0402_hd]
C1231  10pF  [cc0402_hd]
C1232  10pF  [cc0402_hd]
C1261  1uF  [CC0603_OV]
C1262  1uF  [CC0603_OV]
C2704  1uF  [CC0402_HD]
C2705  1uF  [CC0402_HD]
C3893  0.22uF  [CC0402_HD]
C3894  1uF  [cc0402_tol0p2]
C3895  1uF  [cc0402_tol0p2]
C3896  0.22uF  [CC0402_HD]
C3897  1uF  [cc0402_tol0p2]
C3898  1uF  [cc0402_tol0p2]
ESD1  RClamp0531T  [diode_bidir_0402]
ESD2  RClamp0531T  [diode_bidir_0402]
ESD3  RClamp0531T  [diode_bidir_0402]
ESD4  RClamp0531T  [diode_bidir_0402]
ESD5  RClamp0531T  [diode_bidir_0402]
ESD6  RClamp0531T  [diode_bidir_0402]
ESD7  RClamp0531T  [diode_bidir_0402]
ESD8  RClamp0531T  [diode_bidir_0402]
L52  10UH  [ind_2016a]
L53  10UH  [ind_2016a]
LAN1  CON_RJ45  [con16_rj45_jack_50mil_ra_th]  (sections A,B)
R816  0  [RC0402_25]
R817  0  [RC0603_OV]
R1052  33  [RC0402_25]
R1053  33  [RC0402_25]
R1054  33  [RC0402_25]
R1055  33  [RC0402_25]
R1056  33  [RC0402_25]
R1057  33  [RC0402_25]
R1058  33  [RC0402_25]
R1059  33  [RC0402_25]
U46  LTC2804  [DFN16_0P5_3X5]
U95  LTC2804  [DFN16_0P5_3X5]
sheet T4240 DDR Controller #2
U22  T4240NSE7TTB  [BGA1932_1MM_45X45MM]  (sections A,B,C,D,E,F,G,H,I,J,K,L,M,N,O,P,Q,R,S,T)
sheet T4240 USB Ports
C505  0.1uF  [CC0402_HD]
C515  1uF  [CC0402_HD]
C516  1uF  [CC0402_HD]
C518  0.1uF  [CC0402_HD]
C519  0.1uF  [CC0402_HD]
C871  0.01UF  [CC0402_HD]
C5341  330uF  [cap_10p5_rad]
C5342  330uF  [cap_10p5_rad]
CN4  USB_TYPE_A_DUAL  [con_usb_8f_th_ra]
D9  CMHD3595  [sod123_a]
D10  CMHD3595  [sod123_a]
L23  90 OHM@100MHZ  [IND_0805_4P]
L24  90 OHM@100MHZ  [IND_0805_4P]
L26  100 OHM  [IND_0805]
L27  100 OHM  [IND_0805]
R508  17.4K  [RC0402_25]
R659  18K  [RC0402_25]
R660  10.0K  [RC0402_25]
R661  10.0K  [RC0402_25]
R662  51.1K  [RC0402_25]
R663  18K  [RC0402_25]
R664  51.1K  [RC0402_25]
R736  49.9  [RC0402_25]
R741  49.9  [RC0402_25]
R747  10.0K  [RC0402_25]
R761  0  [RC0402_25]
R5725  17.4K  [RC0402_25]
U47  NX5P3090UK  [wlcsp12_0p4_1p38x1p68mm_smdp]
U48  NX5P3090UK  [wlcsp12_0p4_1p38x1p68mm_smdp]
U608  PUSB3AB4  [xson10_0p5_1p1x2p6mm]
U628  74AUP1G04GV  [sot23-5_a]
U629  74AUP1G04GV  [sot23-5_a]

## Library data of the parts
C15-C18 C467 C1266 = CAP_NP: CAP CER 1UF 25V 10% X7R 0603; AGILE_PN: 150-30185; CAD_APPROVED: Yes; FPLIST: CC0603_OV,CC0603,0603_CC; HEIGHT: 0.9mm; MFG_NAME01: WURTH ELEKTRONIK EISOS GMBH & CO. KG (ELECTRONIC & ELECTROMEHANICAL COMP); MFG_PN01: 885012206076; Package: 1206; Package Size: 0603; Package Type: tape & reel; Part Number: 4CC106E251X00; Product Name: (H)MLCC 10uF/25V +-10% 1206 X5R; ROHS: Yes; Rated Voltage: 25V; Temp Range: -55C to +125C; Tolerance: 10%
C3848 = CAP_NP: CAP CER 0.1uF 16V 10% X7R AEC-Q200 0402; AGILE_PN: 150-79025; CAD_APPROVED: Yes; FPLIST: CC0402_25,CC0402_HD,0402_CC,capc0402_l; HEIGHT: 0.55MM; MFG_NAME01: MURATA; MFG_PN01: GCM155R71C104KA55D; PRIORITY_PN: 021-00389; Package Size: 0402; Package Type: ø180mm Reel PAPER; ROHS: Yes; ROOM: I2C1; Rated Voltage: 16V; Temp Range: -55C to +125C; Tolerance: 10%; VOLTAGE: 35V
FAN1-FAN5 = CON_HDR_1X4: HDR 1X4 TH FRICTION LOCK 100MIL SP 430H SN 140L; 3D_Mechanical_Footprint_File: http://fcl.am.freescale.net/ALLEGRO/step/hdr4_2p54_th.step; AGILE_PN: 210-79420; CAD_APPROVED: Yes; FPLIST: hdr4_2p54_th,hdr4_2p54_th_mirror_nsp; HEIGHT: 10.91MM; MFG_NAME01: MOLEX; MFG_PN01: 0022232041; Package Size: 10.2X5.84MM; ROHS: Yes
FAN12 = CON_HDR_1X4: HDR 1X4 TH FRICTION LOCK 100MIL SP 430H SN 140L; 3D_Mechanical_Footprint_File: http://fcl.am.freescale.net/ALLEGRO/step/hdr4_2p54_th.step; AGILE_PN: 210-79420; CAD_APPROVED: Yes; FPLIST: hdr4_2p54_th,hdr4_2p54_th_mirror_nsp; HEIGHT: 10.91MM; MFG_NAME01: MOLEX; MFG_PN01: 0022232041; Package Size: 10.2X5.84MM; ROHS: Yes; SILK: FAN6
R5680-R5689 R5691-R5695 = RES: RES MF 10.0K 1/16W 1% AEC-Q200 0402; AGILE_PN: 470-75416; CAD_APPROVED: Yes; FPLIST: RC0402_25,RC0402_HD,0402_CC; HEIGHT: 0.4MM; MFG_NAME01: KOA SPEER; MFG_PN01: RK73H1ETTP1002F; PRIORITY_PN: 006-00552; ROHS: Yes; ROOM: MII_MUX; Temp Range: –55 °C to +155 °C; Tolerance: 1%
R5690 = RES: RES MF 33K 1/10W 1% AEC-Q200 0402; AGILE_PN: 470-81714; CAD_APPROVED: Yes; FPLIST: RC0402_25,RC0402_HD,0402_CC; HEIGHT: 0.40 MM; MFG_NAME01: KOA SPEER; MFG_PN01: RK73H1ETTP3302F; ROHS: Yes; Temp Range: -55C to +155C; Temp_Range: -55C to +155C; Tolerance: 1%; VOLTAGE: 50V
R5698-R5702 = RES: RES MF 4.7K 1/10W 5% AEC-Q200 0402; AGILE_PN: 470-82064; CAD_APPROVED: Yes; FPLIST: RC0402_25,RC0402_HD,0402_CC,RC0402_X2; HEIGHT: 0.41mm; MFG_NAME01: KOA SPEER; MFG_PN01: RK73B1ETTP472J; ROHS: Yes; SIGNAL_MODEL: DEFAULT_RESISTOR_4700OHM_2_1; TOL: 1%; Temp Range: -55C to +155C; Tolerance: 5%; VOLTAGE: 1/16W
R190-R192 R196 R203 R205 R208 R660 R661 R747 R830 R5790 R5892 = RES: RES MF 10.0K 1/16W 1% AEC-Q200 0402; AGILE_PN: 470-75416; CAD_APPROVED: Yes; FPLIST: RC0402_25,RC0402_HD,0402_CC; HEIGHT: 0.4MM; MFG_NAME01: KOA SPEER; MFG_PN01: RK73H1ETTP1002F; Package: 0402; Part Number: 4RC1003B11X00; Product Name: (H)RES 10K 1/16W 0402 1% PBFREE; ROHS: Yes; Temp Range: –55 °C to +155 °C; Tolerance: 1%
U105 = EMC2305_16P_EP: IC FAN CTRL 5 CHANNEL I2C 3-3.6V QFN16; 3D_Mechanical_Footprint_File: http://fcl.am.freescale.net/ALLEGRO/step/tqfn16_0p65_4X4mm_tab.STEP; AGILE_PN: 312-81742; CAD_APPROVED: Yes; HEIGHT: 0.9MM; MFG_NAME01: MICROCHIP TECHNOLOGY INC; MFG_PN01: EMC2305-1-AP-TR; ROHS: Yes; Temp Range: -40C to 125C; Temp_Range: -40C to 125C; VOLTAGE: 3-3.6V
C7 C112 C113 C144 C505 C518 C519 C1002 C3844 C3847 C5333 C5334 = CAP_NP: CAP CER 0.1uF 16V 10% X7R AEC-Q200 0402; AGILE_PN: 150-79025; CAD_APPROVED: Yes; FPLIST: CC0402_25,CC0402_HD,0402_CC,capc0402_l; HEIGHT: 0.55MM; MFG_NAME01: MURATA; MFG_PN01: GCM155R71C104KA55D; Package: 0402; Package Size: 0402; Package Type: ø180mm Reel PAPER; Part Number: 4CC104B163X00; Product Name: (H)MLCC 0.1uF/16V +-10% 0402 X7R; ROHS: Yes; Rated Voltage: 16V; Temp Range: -55C to +125C; Tolerance: 10%
C5324 = CAP_NP: CAP CER 0.1uF 16V 10% X7R AEC-Q200 0402; AGILE_PN: 150-79025; CAD_APPROVED: Yes; FPLIST: CC0402_25,CC0402_HD,0402_CC,capc0402_l; HEIGHT: 0.55MM; MFG_NAME01: MURATA; MFG_PN01: GCM155R71C104KA55D; PRIORITY_PN: 021-00389; Package Size: 0402; Package Type: ø180mm Reel PAPER; ROHS: Yes; ROOM: XFI; Rated Voltage: 16V; Temp Range: -55C to +125C; Tolerance: 10%; VOLTAGE: 35V
J4 = CONN_HDR_3X1: HDR 1X3 TH 1.27MM SP 335H AU 120L; 3D_Mechanical_Footprint_File: http://fcl.am.freescale.net/ALLEGRO/step/hdr1x3_50mil_335h.STEP; AGILE_PN: 210-83335; CAD_APPROVED: Yes; HEIGHT: 8.509MM; MFG_NAME01: SAMTEC; MFG_PN01: TMS-103-01-L-S; Package Type: PCB, Through Hole; ROHS: Yes; SILK: I2C2; Temp Range: -55°C to 125°C
J55 = CONN_HDR_3X1: HDR 1X3 TH 1.27MM SP 335H AU 120L; 3D_Mechanical_Footprint_File: http://fcl.am.freescale.net/ALLEGRO/step/hdr1x3_50mil_335h.STEP; AGILE_PN: 210-83335; CAD_APPROVED: Yes; HEIGHT: 8.509MM; MFG_NAME01: SAMTEC; MFG_PN01: TMS-103-01-L-S; Package Type: PCB, Through Hole; ROHS: Yes; SILK: I2C1; Temp Range: -55°C to 125°C
R217 R222 = RES: RES MF 4.7K 1/10W 5% AEC-Q200 0402; AGILE_PN: 470-82064; CAD_APPROVED: Yes; FPLIST: RC0402_25,RC0402_HD,0402_CC,RC0402_X2; HEIGHT: 0.41mm; MFG_NAME01: KOA SPEER; MFG_PN01: RK73B1ETTP472J; ROHS: Yes; Temp Range: -55C to +155C; Tolerance: 5%
R519-R523 R526-R531 R5870-R5874 = RES: RES MF 4.7K 1/10W 5% AEC-Q200 0402; AGILE_PN: 470-82064; CAD_APPROVED: Yes; FPLIST: RC0402_25,RC0402_HD,0402_CC,RC0402_X2; HEIGHT: 0.41mm; MFG_NAME01: KOA SPEER; MFG_PN01: RK73B1ETTP472J; PRIORITY_PN: 006-00619; ROHS: Yes; ROOM: DUT_CLOSE; SIGNAL_MODEL: DEFAULT_RESISTOR_4700OHM_2_1; TOL: 1%; Temp Range: -55C to +155C; Tolerance: 5%; VOLTAGE: 1/16W
U18 U58 = PCA9507DP_TSSOP8: IC LEVEL SHIFTER I2C-BUS 2.7-5.5V TSSOP8; 3D_Mechanical_Footprint_File: http://fcl.am.freescale.net/ALLEGRO/step/tssop8_a.STEP; AGILE_PN: 312-76975; CAD_APPROVED: Yes; HEIGHT: 1.1 MM; MFG_NAME01: NXP SEMICONDUCTORS; MFG_PN01: PCA9517ADP,118; ROHS: Yes; Temp Range: -55C to +125C
U82 = PCA9547_24P: IC SW I2C WITH RST 8 CH 2.3-5.5V TSSOP24; 3D_Mechanical_Footprint_File: http://fcl.am.freescale.net/ALLEGRO/step/tssop24_0p65_7p9x4p5.STEP; AGILE_PN: 312-80055; CAD_APPROVED: Yes; HEIGHT: 1.1MM; MFG_NAME01: NXP SEMICONDUCTORS; MFG_PN01: PCA9547PW,118; PRIORITY_PN: 051-PCA9547PW; ROHS: Yes; ROOM: XFI
C9 C12 = CAP_NP: CAP CER 1000pF 50V 10% X7R AEC-Q200 0402; AGILE_PN: 150-79040; CAD_APPROVED: Yes; FPLIST: CC0402_25,CC0402_HD,0402_CC,capc0402_l; HEIGHT: 0.55MM; MFG_NAME01: MURATA; MFG_PN01: GCM155R71H102KA37D; Package: 0402; Package Size: 0402; Package Type: Paper Tape; Part Number: 4CC102B501X00; Product Name: (H)MLCC 0.001uF/50V +-10% 0402 X7R PBFREE; ROHS: Yes; Rated Voltage: 50V; Temp Range: -55C to +125C; Tolerance: 10%
C1158 = CAP_NP: CAP CER 1uF 10V 10% X7S 0402; AGILE_PN: 150-80357; CAD_APPROVED: Yes; FPLIST: CC0402_25,CC0402_HD,0402_CC,capc0402_l; HEIGHT: 0.6MM; MFG_NAME01: MURATA; MFG_PN01: GRM155C71A105KE11D; Package Size: 0402; ROHS: Yes; ROOM: DUT_CLOSE; Rated Voltage: 10V; Temp Range: -55C to +125C; Tolerance: 10%; VOLTAGE: 6.3V
C5345 = CAP_POL: CAP ACTVTD CRBN 1F 5.5V +80/-20% -- RADIAL; 3D_Mechanical_Footprint_File: http://fcl.am.freescale.net/ALLEGRO/step/cap_5x19p2_th.step; AGILE_PN: 150-80363; CAD_APPROVED: Yes; HEIGHT: 19.5MM; MFG_NAME01: EATON; MFG_PN01: KR-5R5V105-R; ROHS: Yes; Rated Voltage: 5.5V; Temp Range: -25C to +70C; Tolerance: -20%, +80%
D46 = DIODE_SCHTKY: DIODE SW 215mA 75V AEC-Q101 SOD123; AGILE_PN: 480-80068; CAD_APPROVED: Yes; HEIGHT: 1.3MM; MFG_NAME01: NEXPERIA; MFG_PN01: BAS116GWX; Temp Range: -55° C to + 150° C
R30 R35 R36 R51 = RES: RES MF 10.0 OHM 1/16W 1% 0402; 3D_Mechanical_Footprint_File: http://fcl.am.freescale.net/ALLEGRO/step/rc0402_25.STEP; AGILE_PN: 470-76090; CAD_APPROVED: Yes; FPLIST: RC0402_25,RC0402_HD,0402_CC; HEIGHT: 0.4MM; MFG_NAME01: BOURNS; MFG_PN01: CR0402-FX-10R0GLF; PRIORITY_PN: 006-00651; ROHS: Yes; ROOM: I2C1_CH2; SIGNAL_MODEL: RES_RC0402_25_DISCRETE_470-7609_10.0; Tolerance: 1%
R1969 = RES: RES MF 330 OHM 1/16W 5% 0402; AGILE_PN: 470-75613; CAD_APPROVED: Yes; FPLIST: RC0402_25,RC0402_HD,0402_CC; HEIGHT: 0.41mm; MFG_NAME01: BOURNS; MFG_PN01: CR0402-JW-331GLF; ROHS: Yes; SIGNAL_MODEL: DEFAULT_RESISTOR_330OHM_2_1; TOL: 5%; Tolerance: 5%
R5907 = RES: RES MF 4.70K 1/16W 1% 0402; AGILE_PN: 470-75418; CAD_APPROVED: Yes; FPLIST: RC0402_25,RC0402_HD,0402_CC; HEIGHT: 0.4mm; MFG_NAME01: WALSIN TECHNOLOGY CORP.; MFG_PN01: WR04X4701FTL; PRIORITY_PN: 006-00619; ROHS: Yes; ROOM: FPGA; Tolerance: 1%; VOLTAGE: 1/16W
TP115 TP289 = T_POINT_TH: TEST POINT PAD 20 MILS SMT, NOT PART TO ORDER; AGILE_PN: 211-81036; CAD_APPROVED: Yes; FPLIST: tpad_020_top,tpad_020_btm_nsp; HEIGHT: 0.127MM; MFG_NAME01: NO PART ORDER; MFG_PN01: NA; ROHS: Yes
U2 = ADT7481: IC DUAL CHN TEMP SENSOR -0.3 to +3.6V MSOP10; 3D_Mechanical_Footprint_File: http://fcl.am.freescale.net/ALLEGRO/step/msop10_60x12.STEP; AGILE_PN: 312-80122; CAD_APPROVED: Yes; HEIGHT: 1.10MM; MFG_NAME01: ON SEMICONDUCTOR; MFG_PN01: ADT7481ARMZ-REEL; ROHS: Yes
U16 = PCF2131: IC RTC CALENDAR W/XTAL TCXO 3.3V AEC-Q100 SO16; AGILE_PN: 312-82330; CAD_APPROVED: Yes; HEIGHT: 1.75MM; MFG_NAME01: NXP SEMICONDUCTORS; ROHS: Yes
U589 U625 = 24AA025E_EEPROM_8P: IC MEM EEPROM 32BIT 400KHz 1.7-5.5V SOIC8; 3D_Mechanical_Footprint_File: http://fcl.am.freescale.net/ALLEGRO/step/so8_1p27_4x5.step; AGILE_PN: 334-77782; CAD_APPROVED: Yes; HEIGHT: 1.75MM; MFG_NAME01: MICROCHIP TECHNOLOGY INC; ROHS: Yes; Temp Range: -40C to +85C; VOLTAGE: 1.7-5.5V
LED1-LED4 = LED: LED BRIGHT GRN SGL 30mA 0603; AGILE_PN: 370-76670; CAD_APPROVED: Yes; HEIGHT: 0.8 MM; MFG_NAME01: WURTH ELEKTRONIK EISOS GMBH & CO. KG (ELECTRONIC & ELECTROMEHANICAL COMP); MFG_PN01: 150060VS75000
LED5 LED6 = LED_DUAL_GG: LED GRN GRN DUAL RA 10MA TH; 3D_Mechanical_Footprint_File: http://fcl.am.freescale.net/ALLEGRO/step/led_dual_553_th.step; AGILE_PN: 370-76674; CAD_APPROVED: Yes; HEIGHT: 10.16MM; MFG_NAME01: DIALIGHT; MFG_PN01: 553-0122F
Q3-Q10 = NMOS_NX3008NBK: TRAN NMOS SW 30V 350mA AEC-Q101 SC-70; 3D_Mechanical_Footprint_File: http://fcl.am.freescale.net/ALLEGRO/step/sc70_3.STEP; AGILE_PN: 480-79736; CAD_APPROVED: Yes; HEIGHT: 1.1MM; MFG_NAME01: NEXPERIA; ROHS: Yes
R332 R333 R335 R341 = RES: RES 1K 1/16W 5% 0402; AGILE_PN: 470-80721; CAD_APPROVED: Yes; FPLIST: RC0402_25,RC0402_HD,0402_CC; HEIGHT: 0.4 MM; MFG_NAME01: TE CONNECTIVITY LTD; MFG_PN01: CRG0402J1K0; Package: 0402; Part Number: 4RC1002B11X00; Product Name: (H)RES 1K 1/16W 0402 1% PBFREE; ROHS: Yes; Tolerance: 5%
R992-R995 = RES: RES MF 330 OHM 1/16W 5% 0402; AGILE_PN: 470-75613; CAD_APPROVED: Yes; FPLIST: RC0402_25,RC0402_HD,0402_CC; HEIGHT: 0.41mm; MFG_NAME01: BOURNS; MFG_PN01: CR0402-JW-331GLF; Package: 0603; Part Number: 4RC3301C11X00; Product Name: (H)RES 330E 1/10W 0603 1% PBFREE; ROHS: Yes; Tolerance: 5%
C1224-C1227 C1229-C1232 = CAP_NP: CAP CER 10pF 50V 1% C0G AEC-Q200 0402; 3D_Mechanical_Footprint_File: http://fcl.am.freescale.net/ALLEGRO/step/cc0402_25.STEP; AGILE_PN: 150-81416; CAD_APPROVED: Yes; FPLIST: cc0402_25,cc0402_hd,0402_cc,capc0402_l; HEIGHT: 0.55MM; MFG_NAME01: MURATA; MFG_PN01: GCM1555C1H100FA16; Package: 0402; Package Size: 0402; Package Type: SMD/SMT; Part Number: 4CC100B501X00; Product Name: (H)MLCC 10pF/50V +-0.5pF 0402 NPO PBFREE; ROHS: Yes; Rated Voltage: 50V; Temp Range: -55C to +125C; Tolerance: 1%
C1261 C1262 = CAP_NP: CAP CER 1UF 25V 10% X7R 0603; AGILE_PN: 150-30185; CAD_APPROVED: Yes; FPLIST: CC0603_OV,CC0603,0603_CC; HEIGHT: 0.9mm; MFG_NAME01: WURTH ELEKTRONIK EISOS GMBH & CO. KG (ELECTRONIC & ELECTROMEHANICAL COMP); MFG_PN01: 885012206076; Package: 0805; Package Size: 0603; Package Type: tape & reel; Part Number: 4CC105D162X00; Product Name: (H)MLCC 1uF/16V +-10% 0805 X5R PBFREE; ROHS: Yes; Rated Voltage: 25V; Temp Range: -55C to +125C; Tolerance: 10%
C2704 C2705 = CAP_NP: CAP CER 1uF 10V 10% X7S 0402; AGILE_PN: 150-80357; CAD_APPROVED: Yes; FPLIST: CC0402_25,CC0402_HD,0402_CC,capc0402_l; HEIGHT: 0.6MM; MFG_NAME01: MURATA; MFG_PN01: GRM155C71A105KE11D; PRIORITY_PN: 021-00242; Package Size: 0402; ROHS: Yes; ROOM: DUT_CLOSE; Rated Voltage: 10V; SIGNAL_MODEL: DEFAULT_CAPACITOR_1e+06pF_2_1; TOL: 10%; Temp Range: -55C to +125C; Tolerance: 10%; VOLTAGE: 10V
C3893 C3896 = CAP_NP: CAP CER 0.22uF 10V 10% X7R AEC-Q200 0402; 3D_Mechanical_Footprint_File: http://fcl.am.freescale.net/ALLEGRO/step/cc0402_25.STEP; AGILE_PN: 150-79031; CAD_APPROVED: Yes; FPLIST: CC0402_25,CC0402_HD,0402_CC,capc0402_l; HEIGHT: 0.55MM; MFG_NAME01: MURATA; MFG_PN01: GRT155R71A224KE01D; ROHS: Yes; ROOM: RS232; Rated Voltage: 10V; SIGNAL_MODEL: DEFAULT_CAPACITOR_220000pF_2_1; TOL: 10%; Temp Range: -55C to +125C; Tolerance: 10%; VOLTAGE: 16V
C3894 C3895 C3897 C3898 = CAP_NP: CAP CER 1uF 10V 10% X7S AEC-Q200 0402; AGILE_PN: 150-79497; CAD_APPROVED: Yes; FPLIST: cc0402_tol0p2,cc0402_tol0p2_ov,cc0402_25_tol0p2,0402_cc_nsp; HEIGHT: 0.7MM; MFG_NAME01: MURATA; MFG_PN01: GCM155C71A105KE38D; Package Size: 0402; ROHS: Yes; Rated Voltage: 10V; Temp Range: -55C to +125C; Tolerance: 10%; VOLTAGE: 16V
ESD1-ESD8 = DIODE_TVS_BIDIR: DIODE TVS ESD PROTECTION 40A 5V 0402; 3D_Mechanical_Footprint_File: http://fcl.am.freescale.net/ALLEGRO/step/diode_bidir_0402_17h.STEP; AGILE_PN: 480-78560; CAD_APPROVED: Yes; HEIGHT: 0.43MM; MFG_NAME01: SEMTECH CORP; MFG_PN01: RClamp0531T.TCT; Rated Voltage: 5V
L52 L53 = INDUCTOR: IND FER 10UH 245MA 20% 0806; AGILE_PN: 180-76880; CAD_APPROVED: Yes; HEIGHT: 1.8MM; MFG_NAME01: TAIYO YUDEN; MFG_PN01: LBC2016T100M; PRIORITY_PN: 024-00181; ROHS: Yes; ROOM: RS232; SIGNAL_MODEL: DEFAULT_INDUCTOR_10000nH_2_1; TOL: 20%; Tolerance: 20%
LAN1 = CON16_RJ45_JACK: CON 16 RJ45 MODULAR JACK RA TH 2.54MM 1006H AU 126L; 3D_Mechanical_Footprint_File: http://fcl.am.freescale.net/ALLEGRO/step/con16_rj45_jack_50mil_ra_th.step; AGILE_PN: 211-83365; CAD_APPROVED: Yes; HEIGHT: 25.55MM; MFG_NAME01: CUI Devices; MFG_PN01: CRJ035-3-TH; Package Type: Through Hole; ROHS: Yes; Temp Range: 0C - 70C
R816 = RES: RES MF ZERO OHM 1/10W -- 0402; AGILE_PN: 470-79965; CAD_APPROVED: Yes; FPLIST: RC0402_25,RC0402_HD,RC0402_X2,0402_CC,RC0402_X3; HEIGHT: 0.4MM; MFG_NAME01: PANASONIC; MFG_PN01: ERJ-2GE0R00X; Package: 0603; Part Number: 4RC0000C51X00; Product Name: (H)RES 0E 1/10W 0603 5% PBFREE; ROHS: Yes; Temp Range: –55 °C to +155 °C
R817 = RES: RES MF ZERO OHM 1/10W AEC-Q200 0603; AGILE_PN: 470-82905; CAD_APPROVED: Yes; FPLIST: RC0603_OV,RC0603,0603_CC; HEIGHT: 0.55 MM; MFG_NAME01: YAGEO AMERICA; MFG_PN01: AC0603FR-070RL; Package: 0603; Part Number: 4RC0000C51X00; Product Name: (H)RES 0E 1/10W 0603 5% PBFREE; ROHS: Yes; Temp Range: -55 °C to +155 °C
R1052-R1059 = RES: RES MF 33 OHM 1/10W 5% AEC-Q200 0402; AGILE_PN: 470-82134; CAD_APPROVED: Yes; FPLIST: RC0402_25,RC0402_HD,0402_CC; HEIGHT: 0.4MM; MFG_NAME01: KOA SPEER; MFG_PN01: RK73B1ETTP330J; Package: 0402; Part Number: 4RC3300B11X00; Product Name: (H)RES 33E 1/16W 0402 1% PBFREE; ROHS: Yes; Temp Range: -55&#8451; to 155&#8451;; Tolerance: 5%
U46 U95 = LTC2804IDHC: IC XCVR RS232 DUAL 1.8-5.5V DFN16; 3D_Mechanical_Footprint_File: http://fcl.am.freescale.net/ALLEGRO/step/dfn16_0p5_3x5.STEP; AGILE_PN: 312-81124; CAD_APPROVED: Yes; HEIGHT: 0.8 MM; MFG_NAME01: ANALOG DEVICES; MFG_PN01: LTC2804CDHC#PBF; ROHS: Yes; VOLTAGE: 1.8-5.5V
U22 = T4240: IC MPU 64BIT T4240 1.8GHz 1.025V CRYPTO QorIQ PBGA1932; 3D_Mechanical_Footprint_File: http://fcl.am.freescale.net/ALLEGRO/step/bga1932_1mm_45x45mm.STEP; AGILE_PN: 330-77243; CAD_APPROVED: Yes; HEIGHT: 3.33 MM; MFG_NAME01: NXP SEMICONDUCTOR; Package Size: SOT1645-1; Part Number: 71F101G206X01; Product Name: (N)SOC FREESCALE:T4240NSE7TTB; ROHS: Yes; Temp Range: 0 to 105 °C
C515 C516 = CAP_NP: CAP CER 1uF 10V 10% X7S 0402; AGILE_PN: 150-80357; CAD_APPROVED: Yes; FPLIST: CC0402_25,CC0402_HD,0402_CC,capc0402_l; HEIGHT: 0.6MM; MFG_NAME01: MURATA; MFG_PN01: GRM155C71A105KE11D; Package Size: 0402; ROHS: Yes; Rated Voltage: 10V; SIGNAL_MODEL: DEFAULT_CAPACITOR_1e+06pF_2_1; Temp Range: -55C to +125C; Tolerance: 10%; VOLTAGE: 10V
C871 = CAP_NP: CAP CER 0.01UF 50V 10% X7R 0402; AGILE_PN: 150-30114; CAD_APPROVED: Yes; FPLIST: CC0402_25,CC0402_HD,0402_CC,capc0402_l; HEIGHT: 0.55 MM; MFG_NAME01: MURATA; MFG_PN01: GRM155R71H103KA88D; Package: 0402; Part Number: 4CC103B161X00; Product Name: (H)MLCC 0.01uF/16V +-10% 0402 X7R PBFREE; ROHS: Yes; Rated Voltage: 50V; Temp Range: -55C to +125C; Tolerance: 10%
C5341 C5342 = CAP_POL: CAP ALEL 330uF 25V 20% -- RADIAL; AGILE_PN: 150-78978; CAD_APPROVED: Yes; ESR: 0.014 OHMS; HEIGHT: 13 MM; MFG_NAME01: PANASONIC; MFG_PN01: 25SEPF330M; ROHS: Yes; ROOM: VDD_GVDD_PS; Rated Voltage: 25V; Temp Range: -55C to +150C; Temp_Range: –55 °C to +105 °C; Tolerance: 20%; VOLTAGE: 25V
CN4 = CON_USB_8P_F_4SH: CON 1X4 DUAL USB_TYPE_A_FEMALE RA SHLD TH -- 648H AU 118L; 3D_Mechanical_Footprint_File: http://fcl.am.freescale.net/ALLEGRO/step/con_usb_8f_th_ra.STEP; AGILE_PN: 210-80091; CAD_APPROVED: Yes; HEIGHT: 16.45MM; MFG_NAME01: SAMTEC; MFG_PN01: USB-A-D-S-B-TH-R; Package Type: TH; ROHS: Yes
D9 D10 = DIODE: DIODE SW 150MA 150V SOD123; 3D_Mechanical_Footprint_File: http://fcl.am.freescale.net/ALLEGRO/step/sod123_a.STEP; AGILE_PN: 480-78080; CAD_APPROVED: Yes; HEIGHT: 1.35MM; MFG_NAME01: CENTRAL SEMICONDUCTOR; MFG_PN01: CMHD3595 BK LEAD FREE; Part Number: 4D00359501X00; Product Name: (N)(C)SILICON DIODE CENTRAL:CMHD3595; ROHS: Yes
L23 L24 = 42H171000: IND CHOKE USB2.0 90OHM@100MHz 500mA SMT 0805; 3D_Mechanical_Footprint_File: http://fcl.am.freescale.net/ALLEGRO/step/ind_0805_4p.STEP; AGILE_PN: 180-77702; CAD_APPROVED: Yes; HEIGHT: 1.65MM; MFG_NAME01: COILCRAFT; MFG_PN01: 0805USB-901MLC; ROHS: Yes
L26 L27 = BEAD: IND FER BEAD 100OHM@100MHZ 4A 25% AEC-Q200 0805; AGILE_PN: 180-78923; CAD_APPROVED: Yes; HEIGHT: 1.05MM; MFG_NAME01: TDK; MFG_PN01: MPZ2012S101ATD25; Package Size: 2x1.25MM; ROHS: Yes; Temp Range: -55°C to +125°C
R508 R5725 = RES: RES MF 17.4K 1/10W 1% AEC-Q200 0402; AGILE_PN: 470-30972; CAD_APPROVED: Yes; FPLIST: RC0402_25,RC0402_HD,0402_CC; HEIGHT: 0.40 MM; MFG_NAME01: KOA SPEER; MFG_PN01: RK73H1ETTP1742F; ROHS: Yes; Temp Range: -55C to +155C; Temp_Range: -55C to +155C; Tolerance: 1%; VOLTAGE: 50V
R659 R663 = RES: RES MF 18K 1/10W 1% AEC-Q200 0402; AGILE_PN: 470-81693; CAD_APPROVED: Yes; FPLIST: RC0402_25,RC0402_HD,0402_CC; HEIGHT: 0.40 MM; MFG_NAME01: KOA SPEER; MFG_PN01: RK73H1ETTP1802F; Package: 0402; Part Number: 4RC1803B11X00; Product Name: (H)RES 18K 1/16W 0402 1%; ROHS: Yes; Temp Range: -55C to +155C; Tolerance: 1%
R662 R664 = RES: RES MF 51.1K 1/10W 1% AEC-Q200 0402; AGILE_PN: 470-81733; CAD_APPROVED: Yes; FPLIST: RC0402_25,RC0402_HD,0402_CC; HEIGHT: 0.40 MM; MFG_NAME01: KOA SPEER; MFG_PN01: RK73H1ETTP5112F; Package: 0603; Part Number: 4RC5113C11X00; Product Name: (H)RES 51.1K 1/10W 0603 1%; ROHS: Yes; Temp Range: -55C to +155C; Tolerance: 1%
R736 R741 = RES: RES MF 49.9 OHM 1/10W 1% AEC-Q200 0402; AGILE_PN: 470-82539; CAD_APPROVED: YES; FPLIST: RC0402_25,RC0402_HD,0402_CC,RC0402_X2; HEIGHT: 0.4 MM; MFG_NAME01: PANASONIC; MFG_PN01: ERJ-2RKF49R9X; Package: 0402; Package Size: 0402 (1005 Metric); Part Number: 4RC4990B11X00; Product Name: (H)RES 49.9E 1/16W 0402 1% PBFREE; ROHS: YES; Temp Range: -55°C to 155°C; Tolerance: 1%
R761 = RES: RES MF ZERO OHM 1/10W -- 0402; AGILE_PN: 470-79965; CAD_APPROVED: Yes; FPLIST: RC0402_25,RC0402_HD,RC0402_X2,0402_CC,RC0402_X3; HEIGHT: 0.4MM; MFG_NAME01: PANASONIC; MFG_PN01: ERJ-2GE0R00X; Package: 0402; Part Number: 4RC0000B51X00; Product Name: (H)RES 0E 1/16W 0402 5% PBFREE; ROHS: Yes; Temp Range: –55 °C to +155 °C
U47 U48 = NX5P3090UK_WLCSP12: IC USB PD TYPE C CURRENT LIMITED PWR SW 2.5-5.5V WLCSP12; 3D_Mechanical_Footprint_File: http://fcl.am.freescale.net/ALLEGRO/step/wlcsp12_0p4_1p38x1p68mm_smdp.STEP; AGILE_PN: 312-81574; CAD_APPROVED: Yes; HEIGHT: 0.565 MM; MFG_NAME01: NXP SEMICONDUCTORS; MFG_PN01: NX5P3090UK,012; ROHS: Yes
U608 = DIODE_ESD_4CH_PUSB3AB4: DIODE ARRAY ESD 3.3V 7A DFN2510A-10; 3D_Mechanical_Footprint_File: http://fcl.am.freescale.net/ALLEGRO/step/xson10_0p5_1p1x2p6mm.step; AGILE_PN: 480-78994; CAD_APPROVED: Yes; HEIGHT: 0.5MM; MFG_NAME01: NEXPERIA; MFG_PN01: PUSB3AB4Z; ROHS: Yes
U628 U629 = 74AUP1G04GV: IC BUF INV SGL SCHMITT TRIGGER 0.8-3.6V SC74; 3D_Mechanical_Footprint_File: http://fcl.am.freescale.net/ALLEGRO/step/sot23-5_a.STEP; AGILE_PN: 312-81237; CAD_APPROVED: Yes; HEIGHT: 1.1MM; MFG_NAME01: NEXPERIA; MFG_PN01: 74AUP1G04GV,125; ROHS: Yes; VOLTAGE: 0.8-3.6V

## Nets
3V3_SB: C7.1 D46.A R332.1 R333.1 R335.1 R341.1 R992.1 R993.1 R994.1 R995.1 R1969.1 U2.1(VDD) ; also on sheet 7 9 10 47 48
GND: C7.2 C15.2 C16.2 C17.2 C18.2 C112.2 C113.2 C144.2 C467.2 C505.2 C515.2 C516.2 C518.2 C519.2 C871.1 C1002.2 C1158.2 C1261.2 C1262.2 C1266.2 C2704.2 C2705.2 C3844.2 C3847.2 C3848.2 C3894.2 C3895.2 C3897.2 C3898.2 C5324.2 C5333.2 C5334.2 C5341.2 C5342.2 C5345.2 CN4.A4(GND1) CN4.B4(GND2) FAN1.1 FAN2.1 FAN3.1 FAN4.1 FAN5.1 FAN12.1 J4.2 J55.2 Q3.2(SOURCE) Q4.2(SOURCE) Q5.2(SOURCE) Q6.2(SOURCE) Q7.2(SOURCE) Q8.2(SOURCE) Q9.2(SOURCE) Q10.2(SOURCE) R508.2 R659.2 R663.2 R736.2 R741.2 R747.2 R816.1 R817.1 R5698.2 R5699.2 R5700.2 R5701.2 R5702.2 R5725.2 U2.5(GND) U16.3(SDI) U16.7(VSS) U16.17(GND) U18.4(GND) U46.8(GND) U47.B3(GND1) U47.C3(GND2) U47.D3(GND3) U48.B3(GND1) U48.C3(GND2) U48.D3(GND3) U58.4(GND) U82.12(VSS) U95.8(GND) U105.17(GND) U589.1(A0) U589.2(A1) U589.3(A2) U589.4(VSS) U608.3(GND1) U608.8(GND2) U625.4(VSS) U628.3(GND) U629.3(GND) ; also on sheet 6 7 8 9 10 11 12 13 14 15 16 18 19 20 21 22 24 25 27 28 29 30 31 32 33 34 35 36 37 38 39 40 41 42 43 44 45 46 47 48
VBUS_POWER1: D9.C(CATHODE) L26.1 R662.1 U48.C2(VBUS1) U48.D1(VBUS2) U48.D2(VBUS3)
VBUS_POWER2: D10.C(CATHODE) L27.1 R664.1 U47.C2(VBUS1) U47.D1(VBUS2) U47.D2(VBUS3)
VCC_3.3: C113.1 C505.1 C1002.1 C3844.1 C3848.1 C5324.1 C5333.1 R191.1 R192.1 R203.1 R217.1 R222.1 R519.1 R520.1 R521.1 R522.1 R523.1 R526.1 R527.1 R528.1 R529.1 R530.1 R531.1 R660.1 R661.1 R830.1 R5680.1 R5681.1 R5682.1 R5683.1 R5684.1 R5690.1 R5790.1 R5870.1 R5871.1 R5872.1 R5873.1 R5874.1 R5892.1 U18.8(VCCB) U58.8(VCCB) U82.1(A0) U82.2(A1) U82.21(A2) U82.24(VDD) U105.3(VDD) U589.8(VCC) U625.1(A0) U625.2(A1) U625.3(A2) U625.8(VCC) U628.5(VCC) U629.5(VCC) ; also on sheet 6 12 13 16 18 24 25 31 32 33 36 39 40 41 42 43 44 47 48
VCC_5: C515.1 C516.1 U47.B1(VINT1) U47.B2(VINT2) U47.C1(VINT3) U48.B1(VINT1) U48.B2(VINT2) U48.C1(VINT3) ; also on sheet 6 12
VCC_12: C15.1 C16.1 C17.1 C18.1 C467.1 C1266.1 FAN1.2 FAN2.2 FAN3.2 FAN4.2 FAN5.2 FAN12.2 R5685.1 R5686.1 R5687.1 R5688.1 R5689.1 ; also on sheet 6 11 14 15 47 48
VCC_DVDD: C112.1 C144.1 C2704.1 C2705.1 L52.1 L53.1 R190.1 R196.1 R205.1 R208.1 U18.1(VCCA) U46.5(VCC) U46.10(PS) U46.11(MODE) U46.12(VL) U58.1(VCCA) U95.5(VCC) U95.10(PS) U95.11(MODE) U95.12(VL) ; also on sheet 20 27
10G_LAN_GPIO0_N: LED6.1(CATHODE1) Q3.3(DRAIN)
10G_LAN_GPIO1_N: LED6.3(CATHODE2) Q4.3(DRAIN)
10G_LAN_GPIO2_N: LED5.1(CATHODE1) Q5.3(DRAIN)
10G_LAN_GPIO3_N: LED5.3(CATHODE2) Q6.3(DRAIN)
CGND: C1261.1 C1262.1 CN4.M1 CN4.M2 CN4.M3 CN4.M4 LAN1.S1 LAN1.S2 LAN1.S3 LAN1.S4 LAN1.S5 LAN1.S6 ; also on sheet 36 40 44
CLK_USB: R761.2 ; also on sheet 24
CLK_USB_DUT: C871.2 R761.1 U22.E34(USBCLK)
DEBUG_LED1_B: LED1.C(CATHODE) Q7.3(DRAIN)
DEBUG_LED2_B: LED2.C(CATHODE) Q8.3(DRAIN)
DEBUG_LED3_B: LED3.C(CATHODE) Q9.3(DRAIN)
DEBUG_LED4_B: LED4.C(CATHODE) Q10.3(DRAIN)
DUT_UART1_CTS_B: U46.16(R1OUT) ; also on sheet 27
DUT_UART1_RTS_B: U46.13(T2IN) ; also on sheet 27
DUT_UART1_RXD: U46.15(R2OUT) ; also on sheet 27
DUT_UART1_TXD: U46.14(T1IN) ; also on sheet 27
DUT_UART2_CTS_B: U95.16(R1OUT) ; also on sheet 27
DUT_UART2_RTS_B: U95.13(T2IN) ; also on sheet 27
DUT_UART2_RXD: U95.15(R2OUT) ; also on sheet 27
DUT_UART2_TXD: U95.14(T1IN) ; also on sheet 27
FAN1_PWM: FAN1.4 R5680.2 U105.5(PWM1)
FAN1_TACH: FAN1.3 R5685.2 R5691.2
FAN2_PWM: FAN2.4 R5681.2 U105.7(PWM2)
FAN2_TACH: FAN2.3 R5686.2 R5692.2
FAN3_PWM: FAN3.4 R5682.2 U105.9(PWM3)
FAN3_TACH: FAN3.3 R5687.2 R5693.2
FAN4_PWM: FAN4.4 R5683.2 U105.13(PWM4)
FAN4_TACH: FAN4.3 R5688.2 R5694.2
FAN5_PWM: FAN5.4 R5684.2 U105.15(PWM5)
FAN5_TACH: FAN5.3 R5689.2 R5695.2
FAN_ADDR: R5690.2 U105.4(ADDR_SEL)
FAN_DEF: R5790.2 U105.11(CLK)
I2C1_CH0_SCL: R519.2 U82.5(SC0) ; also on sheet 38
I2C1_CH0_SDA: R520.2 U82.4(SD0) ; also on sheet 38
I2C1_CH1_SCL: R521.2 U82.7(SC1) ; also on sheet 40
I2C1_CH1_SDA: R522.2 U82.6(SD1) ; also on sheet 40
I2C1_CH2_SCL: R523.2 U82.9(SC2) ; also on sheet 40
I2C1_CH2_SDA: R5870.2 U82.8(SD2) ; also on sheet 40
I2C1_CH3_SCL: R5871.2 U82.11(SC3) ; also on sheet 41
I2C1_CH3_SDA: R526.2 U82.10(SD3) ; also on sheet 41
I2C1_CH4_SCL: R527.2 U82.14(SC4) ; also on sheet 41
I2C1_CH4_SDA: R528.2 U82.13(SD4) ; also on sheet 41
I2C1_CH5_SCL: R529.2 U82.16(SC5)
I2C1_CH5_SDA: R530.2 U82.15(SD5)
I2C1_CH6_SCL: R531.2 U82.18(SC6) ; also on sheet 47
I2C1_CH6_SDA: R5872.2 U82.17(SD6) ; also on sheet 47
I2C1_CH7_SCL: R5873.2 U82.20(SC7) ; also on sheet 39
I2C1_CH7_SDA: R5874.2 U82.19(SD7) ; also on sheet 39
I2C1_EN: R830.2 U58.5(EN)
I2C1_PROC_SCL: R208.2 U58.2(SCLA) ; also on sheet 27
I2C1_PROC_SDA: R205.2 U58.3(SDAA) ; also on sheet 27
I2C1_SCL: J55.3 R217.2 U2.10(SCLK) U16.2(SCL) U58.7(SCLB) U82.22(SCL) U105.2(SCL) U589.6(SCL) U625.6(SCL) ; also on sheet 8 12 24 31 32 33
I2C1_SDA: J55.1 R222.2 U2.9(SDATA) U16.5(SDA/~{CE}) U58.6(SDAB) U82.23(SDA) U105.1(SDA) U589.5(SDA) U625.5(SDA) ; also on sheet 8 12 24 31 32 33
I2C2_EN: R191.2 U18.5(EN)
I2C2_PROC_SCL: R196.2 U18.2(SCLA) ; also on sheet 27
I2C2_PROC_SDA: R190.2 U18.3(SDAA) ; also on sheet 27
I2C2_SCL: J4.3 R203.2 U18.7(SCLB) ; also on sheet 48
I2C2_SDA: J4.1 R192.2 U18.6(SDAB) ; also on sheet 48
IRQ_FAN_B: R5892.2 U105.12(ALERT_B) ; also on sheet 8
IRQ_RTC_B: U16.13(~{INTA}) ; also on sheet 8
LED0: Q3.1(GATE) ; also on sheet 8
LED1: Q4.1(GATE) ; also on sheet 8
LED2: Q5.1(GATE) ; also on sheet 8
LED3: Q6.1(GATE) ; also on sheet 8
LED4: Q7.1(GATE) ; also on sheet 8
LED5: Q8.1(GATE) ; also on sheet 8
LED6: Q9.1(GATE) ; also on sheet 8
LED7: Q10.1(GATE) ; also on sheet 8
LV_TACH1: R5691.1 R5698.1 U105.6(TACH1)
LV_TACH2: R5692.1 R5699.1 U105.8(TACH2)
LV_TACH3: R5693.1 R5700.1 U105.10(TACH3)
LV_TACH4: R5694.1 R5701.1 U105.14(TACH4)
LV_TACH5: R5695.1 R5702.1 U105.16(TACH5)
P1_LINKACT_P: LED6.2(ANODE1) R994.2
P2_LINKACT_P: LED6.4(ANODE2) R995.2
P3_LINKACT_P: LED5.2(ANODE1) R992.2
P4_LINKACT_P: LED5.4(ANODE2) R993.2
RST_I2CMUX_B: U82.3(~{RESET}) ; also on sheet 8 39
RTCLK: TP115.1(TP) U16.6(CLKOUT)
RTCTS: TP289.1(TP) U16.8(~{TS1})
RTCVSB: C1158.1 R1969.2 U16.1(IFS) U16.15(VDD)
SER1_CTS_B: R1055.1 U46.1(R1IN)
SER1_CTS_B_T: C1226.1 ESD3.1(A1) LAN1.8_T R1055.2
SER1_GND: C1224.2 C1225.2 C1226.2 C1227.2 ESD1.2(A2) ESD2.2(A2) ESD3.2(A2) ESD4.2(A2) LAN1.4_T R816.2
SER1_RTS_B: R1052.1 U46.4(T2OUT)
SER1_RTS_B_T: C1224.1 ESD1.1(A1) LAN1.1_T R1052.2
SER1_RXD: R1054.1 U46.2(R2IN)
SER1_RXD_T: C1227.1 ESD4.1(A1) LAN1.6_T R1054.2
SER1_TXD: R1053.1 U46.3(T1OUT)
SER1_TXD_T: C1225.1 ESD2.1(A1) LAN1.3_T R1053.2
SER2_CTS_B: R1059.1 U95.1(R1IN)
SER2_CTS_B_T: C1232.1 ESD8.1(A1) LAN1.8_B R1059.2
SER2_GND: C1229.2 C1230.2 C1231.2 C1232.2 ESD5.2(A2) ESD6.2(A2) ESD7.2(A2) ESD8.2(A2) LAN1.4_B R817.2
SER2_RTS_B: R1056.1 U95.4(T2OUT)
SER2_RTS_B_T: C1229.1 ESD5.1(A1) LAN1.1_B R1056.2
SER2_RXD: R1058.1 U95.2(R2IN)
SER2_RXD_T: C1231.1 ESD7.1(A1) LAN1.6_B R1058.2
SER2_TXD: R1057.1 U95.3(T1OUT)
SER2_TXD_T: C1230.1 ESD6.1(A1) LAN1.3_B R1057.2
TEMP_ANODE1_ADT: C9.1 R30.1 U2.2(D1+)
TEMP_ANODE2_ADT: C12.1 R36.1 U2.7(D2+)
TEMP_CATHODE1_ADT: C9.2 R35.1 U2.3(D1-)
TEMP_CATHODE2_ADT: C12.2 R51.1 U2.6(D2-)
TEMP_DIODE1_N: R35.2 ; also on sheet 27
TEMP_DIODE1_P: R30.2 ; also on sheet 27
TEMP_DIODE2_N: R51.2 ; also on sheet 27
TEMP_DIODE2_P: R36.2 ; also on sheet 27
THERM_FAULT_B: U2.4(~{THERM}) ; also on sheet 8
THERM_WARN_B: U2.8(~{ALERT}/~{THERM2}) ; also on sheet 8
UART1_SW: C3893.2 L52.2 U46.7(SW)
UART2_SW: C3896.2 L53.2 U95.7(SW)
USB1_DN: L23.1 U22.J31(USB1_UDM)
USB1_DP: L23.4 U22.K31(USB1_UDP)
USB1_ID: R736.1 U22.L32(USB1_UID)
USB1_ILIM: R5725.1 U48.A3(ILIM)
USB1_ISON: CN4.B2(D-_B) L23.2 U608.4(CH3) U608.7(NC2)
USB1_ISOP: CN4.B3(D+_B) L23.3 U608.5(CH4) U608.6(NC1)
USB1_ISOPWR: C518.1 C5342.1 CN4.B1(VBUS_B) L26.2
USB1_PWREN: U22.E32(USB1_DRVVBUS) U48.A1(EN)
USB1_PWRFAULT: U22.F32(USB1_PWRFAULT) U629.4(Y)
USB1_PWRFLT_B: R661.2 U48.A2(~{FAULT}) U629.2(A)
USB1_VBUSCLMP: D9.A(ANODE) R659.1 R662.2 U22.G32(USB1_VBUSCLMP)
USB2_DN: L24.1 U22.M31(USB2_UDM)
USB2_DP: L24.4 U22.N31(USB2_UDP)
USB2_ID: R741.1 U22.H32(USB2_UID)
USB2_ILIM: R508.1 U47.A3(ILIM)
USB2_ISON: CN4.A2(D-_A) L24.2 U608.1(CH1) U608.10(NC4)
USB2_ISOP: CN4.A3(D+_A) L24.3 U608.2(CH2) U608.9(NC3)
USB2_ISOPWR: C519.1 C5341.1 CN4.A1(VBUS_A) L27.2
USB2_PWREN: U22.A32(USB2_DRVVBUS) U47.A1(EN)
USB2_PWRFAULT: U22.B32(USB2_PWRFAULT) U628.4(Y)
USB2_PWRFLT_B: R660.2 U47.A2(~{FAULT}) U628.2(A)
USB2_VBUSCLMP: D10.A(ANODE) R663.1 R664.2 U22.C32(USB2_VBUSCLMP)
USB_BIAS: R747.1 U22.D31(USB_IBIAS_REXT)
VBBS: C5334.1 U16.14(BBS)
Z4901: LED4.A(ANODE) R341.2
Z4902: LED3.A(ANODE) R335.2
Z4903: LED2.A(ANODE) R333.2
Z4904: LED1.A(ANODE) R332.2
N31148954: C3894.1 U46.6(VDD)
N31148956: C3895.1 U46.17(VEE)
N31149103: C3897.1 U95.6(VDD)
N31149105: C3898.1 U95.17(VEE)
N34325441: C3847.1 D46.C R5907.1 U16.16(VBAT)
N37212649: C5345.1 R5907.2
N39925735: C3893.1 U46.9(CAP)
N39925736: C3896.1 U95.9(CAP)

Not connected (* = marked no-connect by the designer): FAN12 3* 4*; LAN1 2_B* 2_T* 5_B* 5_T* 7_B* 7_T*; U16 4(SDO)* 9(~{TS2})* 10(~{TS3})* 11(~{TS4})* 12(~{INTB})*; U589 7(NC)*; U625 7(NC)*; U628 1(NC)*; U629 1(NC)*

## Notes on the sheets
sheet 49
- USB PORTS
- USB_HVDD
- NOTE: Connections
  to NC pins are permitted
  and allow stub-less routing.
- USB1_UID,USB2_UID
  Resistor installed = Host Mode(default)
  Not installed = Device Mode
- USB_HVDD
- OVDD
- (for EMI)
sheet 50
- I2C BUS TRANSLATION & MUX
- to RETIMER
- to SFP #1
- to SFP #2
- to SFP #3
- I2C Address
  0x77
- to SFP #4
- to PCIex #1
- to SFP monitor/control
sheet 51
- I2C BUS DEVICES
- --------------------------------EEPROM--------------------------------
- I2C Address = 0x50
- --------------------------------SYSTEM ID----------------------------
- I2C Address = 0x57
- --------------------------------THERM--------------------------------
- I2C Address = 0x4C
- --------------------------------RTC------------------------------------
- SUPERCAP INFO
  =======================
  Discharge Time:
    t = C (Vmax - Vmin) / Ic
    t = 1 (3.3 - 1.0) / 500nA
    t = 4600000s = ~53 days
  Time to Initial Full Charge from Discharge:
    t = 5 * C * R
    t = 5 * 1 * 4700
    t = 23500 = ~6.5 hours
- I2C Address = 0x53
sheet 52
- UART PORTS
- TOP
- BOT
sheet 53
- FAN CONTROLLER & HEADERS
- DEFAULT FAN SPEED
  =====================================
  10K= 50%
  NOTE: SW *must* program the EMC2305 within
  2s of power up, or fan speed is 100%
  no matter the resistor strap.
- I2C ADDR=0x4D
sheet 54
- LEDs
sheet 55
- ASSEMBLY INFO
- REF DES
- JUMPER
- PAGE NAME
- JP6
- 1-2
- 051- I2C Devices
- REF DES
- ASSY_OPT
- PAGE NAME
- R748
- DNP
- 006- Power Entry & Mechanical
- JP8
- DNP
- 008- System FPGA IO Ports
- J69,JP7,U250
- DNP
- 009- System FPGA Power+Prog
- R5771
- DNP
- 010- Switches and Config
- C5132,R95
- DNP
- 011- GVDD & OVDD Power
- R42,R628,R629
- DNP
- 012- VDD
- CT24,CT29,CT41,R273
- DNP
- 020- T4240 GVDD+Other Power
- R5762
- DNP
- 027- T4240 System Block + COP
- C485
- DNP
- 036- T4240 SPI / SDHC Port
- R532,R533,R534,R535,R536,
  R537,R538,R539,R730,R731
- DNP
- 037- T4240 SerDes 1 & 2
- R5825,R5826,R5827,R5828,
  R5837,R5838,R5839,R5840
- DNP
- 038- 10G Retimer
- R926,R927,R935,R936
- DNP
- 040- SFP Ports 1&2 + Cage
- R944,R945,R953,R954
- DNP
- 041- SFP Ports 3&4
- R5753,Y20
- DNP
- 042- 88E1543 1G Phy #1
- R5802,Y21
- DNP
- 043- 88E1543 1G Phy #2
- R744
- DNP
- 045- T4240 EMI + RGMII
- C871
- DNP
- 049- T4240 USB Ports
- C1224,C1225,C1226,C1227,
  C1229,C1230,C1231,C1232
- DNP
- 052- Serial Ports
